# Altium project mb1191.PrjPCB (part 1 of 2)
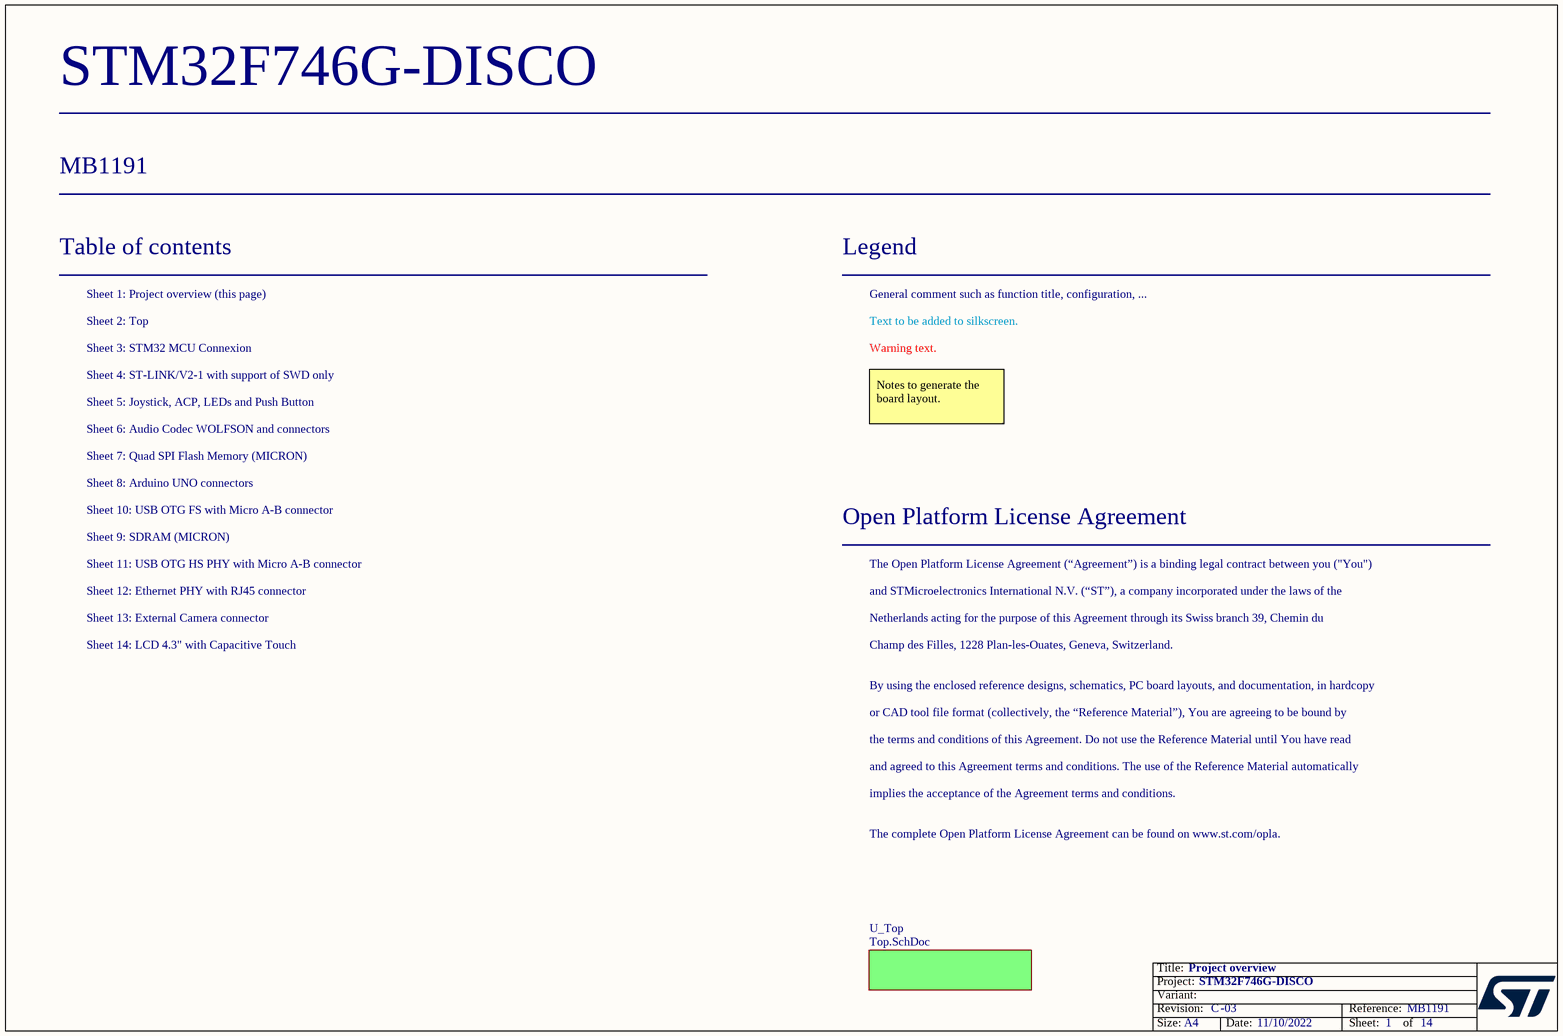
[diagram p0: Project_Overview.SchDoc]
Board_Reference: MB1191; Board_PCB_Revision: C; Board_Name: STM32F746G-DISCO; Board_Document_Date: 11/10/2022; Board_Assembly_Revision: 03
14 sheets, 358 parts. Net scope: flat (ports and power ports of the same name join across sheets).
Board file: MB1191.PcbDoc
Sheets:
  Project_Overview.SchDoc
    U_Top = Top.SchDoc
      U_ST_LINK_V2-1 = ST_LINK_V2-1.SCHDOC
      U_AUDIO = AUDIO.SchDoc
      U_USB_OTG_FS = USB_OTG_FS.SchDoc
      U_Peripherals = Peripherals.SchDoc
      U_QSPI = QSPI.SchDoc
      U_LCD-43 = LCD-43.SchDoc
      U_Arduino_ Connectors = Arduino_ Connectors.SchDoc
      U_SDRAM = SDRAM.SchDoc
      U_USB_OTG_HS = USB_OTG_HS.SchDoc
      U_STM32F7 = STM32F7.SchDoc
      U_Ethernet = Ethernet.SchDoc
      Camera-Connectors = Camera-Connectors.SchDoc

## Sheet Project_Overview.SchDoc: Project overview
size A4; Date: Not used; ApprovedBy: Not used; CheckedBy: Not used; Author: Not used; CompanyName: STMicroelectronics; DrawnBy: Not used; Engineer: Not used; Organization: Not used; Address1: Not used; Address2: Not used; Address3: Not used; Address4: Not used; DocumentNumber: MB1191; Revision: Not used; SheetNumber: 1; SheetTotal: 14

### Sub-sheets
U_Top = Top.SchDoc: no entries

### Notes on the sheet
- Table of contents
- Sheet 1: Project overview (this page)
- Legend
- General comment such as function title, configuration, ...
- Sheet 2: Top
- Sheet 4: ST-LINK/V2-1 with support of SWD only
- Sheet 3: STM32 MCU Connexion
- Text to be added to silkscreen.
- Warning text.
- Sheet 5: Joystick, ACP, LEDs and Push Button
- Sheet 6: Audio Codec WOLFSON and connectors
- Notes to generate the board layout.
- Sheet 8: Arduino UNO connectors
- Sheet 10: USB OTG FS with Micro A-B connector
- Sheet 7: Quad SPI Flash Memory (MICRON)
- Sheet 9: SDRAM (MICRON)
- Sheet 11: USB OTG HS PHY with Micro A-B connector
- Open Platform License Agreement
- The Open Platform License Agreement (“Agreement”) is a binding legal contract between you ("You")
- Sheet 12: Ethernet PHY with RJ45 connector
- Sheet 13: External Camera connector
- Sheet 14: LCD 4.3" with Capacitive Touch
- and STMicroelectronics International N.V. (“ST”), a company incorporated under the laws of the
- Netherlands acting for the purpose of this Agreement through its Swiss branch 39, Chemin du
- Champ des Filles, 1228 Plan-les-Ouates, Geneva, Switzerland.
- By using the enclosed reference designs, schematics, PC board layouts, and documentation, in hardcopy
- or CAD tool file format (collectively, the “Reference Material”), You are agreeing to be bound by
- the terms and conditions of this Agreement. Do not use the Reference Material until You have read
- and agreed to this Agreement terms and conditions. The use of the Reference Material automatically
- implies the acceptance of the Agreement terms and conditions.
- The complete Open Platform License Agreement can be found on www.st.com/opla.

## Sheet Top.SchDoc: STM32F7 Discovery Interconnexion
size A4; Date: 25-FEB-2015; Author: A.B; CompanyName: STMicroelectronics; Address1: 12, Rue Jules HOROWITZ; Address2: 38019 Grenoble; Address3: FRANCE; DocumentNumber: MB1191; Revision: B-02; SheetNumber: 2; SheetTotal: 14; Project: STM32F746G-DISCO
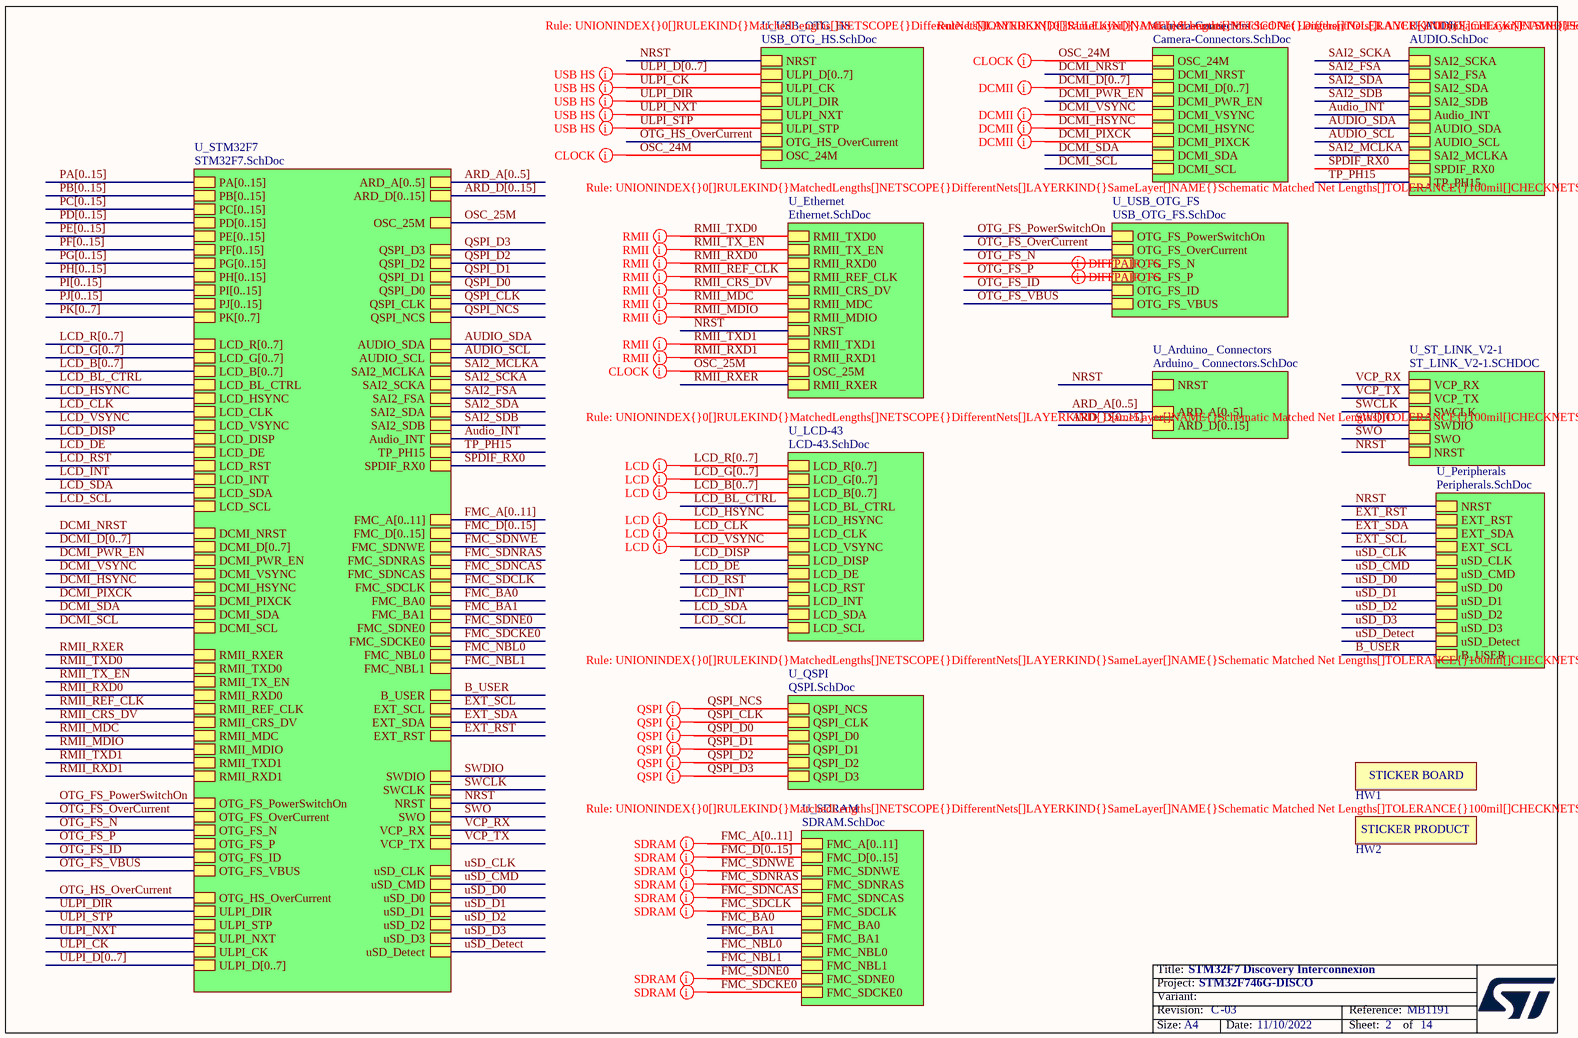
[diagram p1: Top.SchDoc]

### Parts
HW1  STICKER_BOARD  (value not drawn)  (no BOM)
HW2  STICKER_PRODUCT  (value not drawn)  (no BOM)

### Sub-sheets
Camera-Connectors = Camera-Connectors.SchDoc: OSC_24M, DCMI_NRST, DCMI_D[0..7], DCMI_PWR_EN, DCMI_VSYNC, DCMI_HSYNC, DCMI_PIXCK, DCMI_SDA, DCMI_SCL
U_Arduino_ Connectors = Arduino_ Connectors.SchDoc: NRST, ARD_A[0..5], ARD_D[0..15]
U_AUDIO = AUDIO.SchDoc: AUDIO_SDA, AUDIO_SCL, SAI2_MCLKA, SPDIF_RX0, TP_PH15, SAI2_SCKA, SAI2_FSA, SAI2_SDA, SAI2_SDB, Audio_INT
U_Ethernet = Ethernet.SchDoc: RMII_TXD0, RMII_TX_EN, RMII_RXD0, RMII_REF_CLK, RMII_CRS_DV, RMII_MDC, RMII_MDIO, NRST, RMII_TXD1, RMII_RXD1, OSC_25M, RMII_RXER
U_LCD-43 = LCD-43.SchDoc: LCD_R[0..7], LCD_BL_CTRL, LCD_B[0..7], LCD_G[0..7], LCD_HSYNC, LCD_CLK, LCD_VSYNC, LCD_DISP, LCD_DE, LCD_RST, LCD_INT, LCD_SDA, LCD_SCL
U_Peripherals = Peripherals.SchDoc: NRST, EXT_RST, EXT_SCL, EXT_SDA, uSD_CLK, uSD_CMD, uSD_D0, uSD_D1, uSD_D2, uSD_D3, uSD_Detect, B_USER
U_QSPI = QSPI.SchDoc: QSPI_D0, QSPI_D3, QSPI_D1, QSPI_CLK, QSPI_NCS, QSPI_D2
U_SDRAM = SDRAM.SchDoc: FMC_A[0..11], FMC_D[0..15], FMC_SDNWE, FMC_SDNRAS, FMC_SDNCAS, FMC_SDCLK, FMC_BA0, FMC_BA1, FMC_NBL0, FMC_NBL1, FMC_SDNE0, FMC_SDCKE0
U_ST_LINK_V2-1 = ST_LINK_V2-1.SCHDOC: SWDIO, SWCLK, NRST, VCP_RX, VCP_TX, SWO
U_STM32F7 = STM32F7.SchDoc: PA[0..15], PB[0..15], PC[0..15], PD[0..15], PE[0..15], PF[0..15], PG[0..15], PH[0..15], PI[0..15], PJ[0..15], PK[0..7], OSC_25M, LCD_R[0..7], LCD_BL_CTRL, LCD_B[0..7], LCD_G[0..7], LCD_HSYNC, LCD_CLK, LCD_VSYNC, LCD_DISP, LCD_DE, LCD_RST, LCD_INT, LCD_SDA, LCD_SCL, DCMI_NRST, DCMI_D[0..7], DCMI_PWR_EN, DCMI_VSYNC, DCMI_HSYNC, DCMI_PIXCK, DCMI_SDA, DCMI_SCL, RMII_TXD0, RMII_TX_EN, RMII_RXD0, RMII_REF_CLK, RMII_CRS_DV, RMII_MDC, RMII_MDIO, RMII_TXD1, RMII_RXD1, ULPI_D[0..7], ULPI_CK, ULPI_DIR, ULPI_NXT, ULPI_STP, OTG_FS_N, OTG_FS_P, OTG_FS_ID, OTG_FS_VBUS, OTG_FS_PowerSwitchOn, OTG_FS_OverCurrent, QSPI_D0, QSPI_D3, QSPI_D1, QSPI_CLK, QSPI_NCS, AUDIO_SDA, AUDIO_SCL, SAI2_MCLKA, EXT_SCL, EXT_SDA, EXT_RST, uSD_CLK, uSD_CMD, uSD_D0, uSD_D1, uSD_D2, uSD_D3, uSD_Detect, SWDIO, SWCLK, NRST, SWO, VCP_RX, VCP_TX, FMC_A[0..11], FMC_D[0..15], FMC_SDNWE, FMC_SDNRAS, FMC_SDNCAS, FMC_SDCLK, FMC_BA0, FMC_BA1, FMC_SDNE0, FMC_SDCKE0, FMC_NBL0, FMC_NBL1, SPDIF_RX0, QSPI_D2, B_USER, ARD_A[0..5], ARD_D[0..15], RMII_RXER, OTG_HS_OverCurrent, SAI2_SCKA, SAI2_FSA, SAI2_SDA, SAI2_SDB, Audio_INT, TP_PH15
U_USB_OTG_FS = USB_OTG_FS.SchDoc: OTG_FS_PowerSwitchOn, OTG_FS_OverCurrent, OTG_FS_N, OTG_FS_P, OTG_FS_ID, OTG_FS_VBUS
U_USB_OTG_HS = USB_OTG_HS.SchDoc: ULPI_D[0..7], ULPI_CK, ULPI_DIR, ULPI_NXT, ULPI_STP, OSC_24M, NRST, OTG_HS_OverCurrent

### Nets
Audio_INT: sheet U_AUDIO/Audio_INT, sheet U_STM32F7/Audio_INT
AUDIO_SCL: sheet U_AUDIO/AUDIO_SCL, sheet U_STM32F7/AUDIO_SCL
AUDIO_SDA: sheet U_AUDIO/AUDIO_SDA, sheet U_STM32F7/AUDIO_SDA
B_USER: sheet U_Peripherals/B_USER, sheet U_STM32F7/B_USER
DCMI_HSYNC: sheet U_STM32F7/DCMI_HSYNC, sheet Camera-Connectors/DCMI_HSYNC
DCMI_NRST: sheet U_STM32F7/DCMI_NRST, sheet Camera-Connectors/DCMI_NRST
DCMI_PIXCK: sheet U_STM32F7/DCMI_PIXCK, sheet Camera-Connectors/DCMI_PIXCK
DCMI_PWR_EN: sheet U_STM32F7/DCMI_PWR_EN, sheet Camera-Connectors/DCMI_PWR_EN
DCMI_SCL: sheet U_STM32F7/DCMI_SCL, sheet Camera-Connectors/DCMI_SCL
DCMI_SDA: sheet U_STM32F7/DCMI_SDA, sheet Camera-Connectors/DCMI_SDA
DCMI_VSYNC: sheet U_STM32F7/DCMI_VSYNC, sheet Camera-Connectors/DCMI_VSYNC
EXT_RST: sheet U_Peripherals/EXT_RST, sheet U_STM32F7/EXT_RST
EXT_SCL: sheet U_Peripherals/EXT_SCL, sheet U_STM32F7/EXT_SCL
EXT_SDA: sheet U_Peripherals/EXT_SDA, sheet U_STM32F7/EXT_SDA
FMC_BA0: sheet U_SDRAM/FMC_BA0, sheet U_STM32F7/FMC_BA0
FMC_BA1: sheet U_SDRAM/FMC_BA1, sheet U_STM32F7/FMC_BA1
FMC_NBL0: sheet U_SDRAM/FMC_NBL0, sheet U_STM32F7/FMC_NBL0
FMC_NBL1: sheet U_SDRAM/FMC_NBL1, sheet U_STM32F7/FMC_NBL1
FMC_SDCKE0: sheet U_SDRAM/FMC_SDCKE0, sheet U_STM32F7/FMC_SDCKE0
FMC_SDCLK: sheet U_SDRAM/FMC_SDCLK, sheet U_STM32F7/FMC_SDCLK
FMC_SDNCAS: sheet U_SDRAM/FMC_SDNCAS, sheet U_STM32F7/FMC_SDNCAS
FMC_SDNE0: sheet U_SDRAM/FMC_SDNE0, sheet U_STM32F7/FMC_SDNE0
FMC_SDNRAS: sheet U_SDRAM/FMC_SDNRAS, sheet U_STM32F7/FMC_SDNRAS
FMC_SDNWE: sheet U_SDRAM/FMC_SDNWE, sheet U_STM32F7/FMC_SDNWE
LCD_BL_CTRL: sheet U_LCD-43/LCD_BL_CTRL, sheet U_STM32F7/LCD_BL_CTRL
LCD_CLK: sheet U_LCD-43/LCD_CLK, sheet U_STM32F7/LCD_CLK
LCD_DE: sheet U_LCD-43/LCD_DE, sheet U_STM32F7/LCD_DE
LCD_DISP: sheet U_LCD-43/LCD_DISP, sheet U_STM32F7/LCD_DISP
LCD_HSYNC: sheet U_LCD-43/LCD_HSYNC, sheet U_STM32F7/LCD_HSYNC
LCD_INT: sheet U_LCD-43/LCD_INT, sheet U_STM32F7/LCD_INT
LCD_RST: sheet U_LCD-43/LCD_RST, sheet U_STM32F7/LCD_RST
LCD_SCL: sheet U_LCD-43/LCD_SCL, sheet U_STM32F7/LCD_SCL
LCD_SDA: sheet U_LCD-43/LCD_SDA, sheet U_STM32F7/LCD_SDA
LCD_VSYNC: sheet U_LCD-43/LCD_VSYNC, sheet U_STM32F7/LCD_VSYNC
NRST: sheet U_ST_LINK_V2-1/NRST, sheet U_Peripherals/NRST, sheet U_Arduino_ Connectors/NRST, sheet U_USB_OTG_HS/NRST, sheet U_STM32F7/NRST, sheet U_Ethernet/NRST
OSC_24M: sheet U_USB_OTG_HS/OSC_24M, sheet Camera-Connectors/OSC_24M
OSC_25M: sheet U_STM32F7/OSC_25M, sheet U_Ethernet/OSC_25M
OTG_FS_ID: sheet U_USB_OTG_FS/OTG_FS_ID, sheet U_STM32F7/OTG_FS_ID
OTG_FS_N: sheet U_USB_OTG_FS/OTG_FS_N, sheet U_STM32F7/OTG_FS_N
OTG_FS_OverCurrent: sheet U_USB_OTG_FS/OTG_FS_OverCurrent, sheet U_STM32F7/OTG_FS_OverCurrent
OTG_FS_P: sheet U_USB_OTG_FS/OTG_FS_P, sheet U_STM32F7/OTG_FS_P
OTG_FS_PowerSwitchOn: sheet U_USB_OTG_FS/OTG_FS_PowerSwitchOn, sheet U_STM32F7/OTG_FS_PowerSwitchOn
OTG_FS_VBUS: sheet U_USB_OTG_FS/OTG_FS_VBUS, sheet U_STM32F7/OTG_FS_VBUS
OTG_HS_OverCurrent: sheet U_USB_OTG_HS/OTG_HS_OverCurrent, sheet U_STM32F7/OTG_HS_OverCurrent
QSPI_CLK: sheet U_QSPI/QSPI_CLK, sheet U_STM32F7/QSPI_CLK
QSPI_D0: sheet U_QSPI/QSPI_D0, sheet U_STM32F7/QSPI_D0
QSPI_D1: sheet U_QSPI/QSPI_D1, sheet U_STM32F7/QSPI_D1
QSPI_D2: sheet U_QSPI/QSPI_D2, sheet U_STM32F7/QSPI_D2
QSPI_D3: sheet U_QSPI/QSPI_D3, sheet U_STM32F7/QSPI_D3
QSPI_NCS: sheet U_QSPI/QSPI_NCS, sheet U_STM32F7/QSPI_NCS
RMII_CRS_DV: sheet U_STM32F7/RMII_CRS_DV, sheet U_Ethernet/RMII_CRS_DV
RMII_MDC: sheet U_STM32F7/RMII_MDC, sheet U_Ethernet/RMII_MDC
RMII_MDIO: sheet U_STM32F7/RMII_MDIO, sheet U_Ethernet/RMII_MDIO
RMII_REF_CLK: sheet U_STM32F7/RMII_REF_CLK, sheet U_Ethernet/RMII_REF_CLK
RMII_RXD0: sheet U_STM32F7/RMII_RXD0, sheet U_Ethernet/RMII_RXD0
RMII_RXD1: sheet U_STM32F7/RMII_RXD1, sheet U_Ethernet/RMII_RXD1
RMII_RXER: sheet U_STM32F7/RMII_RXER, sheet U_Ethernet/RMII_RXER
RMII_TX_EN: sheet U_STM32F7/RMII_TX_EN, sheet U_Ethernet/RMII_TX_EN
RMII_TXD0: sheet U_STM32F7/RMII_TXD0, sheet U_Ethernet/RMII_TXD0
RMII_TXD1: sheet U_STM32F7/RMII_TXD1, sheet U_Ethernet/RMII_TXD1
SAI2_FSA: sheet U_AUDIO/SAI2_FSA, sheet U_STM32F7/SAI2_FSA
SAI2_MCLKA: sheet U_AUDIO/SAI2_MCLKA, sheet U_STM32F7/SAI2_MCLKA
SAI2_SCKA: sheet U_AUDIO/SAI2_SCKA, sheet U_STM32F7/SAI2_SCKA
SAI2_SDA: sheet U_AUDIO/SAI2_SDA, sheet U_STM32F7/SAI2_SDA
SAI2_SDB: sheet U_AUDIO/SAI2_SDB, sheet U_STM32F7/SAI2_SDB
SPDIF_RX0: sheet U_AUDIO/SPDIF_RX0, sheet U_STM32F7/SPDIF_RX0
SWCLK: sheet U_ST_LINK_V2-1/SWCLK, sheet U_STM32F7/SWCLK
SWDIO: sheet U_ST_LINK_V2-1/SWDIO, sheet U_STM32F7/SWDIO
SWO: sheet U_ST_LINK_V2-1/SWO, sheet U_STM32F7/SWO
TP_PH15: sheet U_AUDIO/TP_PH15, sheet U_STM32F7/TP_PH15
ULPI_CK: sheet U_USB_OTG_HS/ULPI_CK, sheet U_STM32F7/ULPI_CK
ULPI_DIR: sheet U_USB_OTG_HS/ULPI_DIR, sheet U_STM32F7/ULPI_DIR
ULPI_NXT: sheet U_USB_OTG_HS/ULPI_NXT, sheet U_STM32F7/ULPI_NXT
ULPI_STP: sheet U_USB_OTG_HS/ULPI_STP, sheet U_STM32F7/ULPI_STP
uSD_CLK: sheet U_Peripherals/uSD_CLK, sheet U_STM32F7/uSD_CLK
uSD_CMD: sheet U_Peripherals/uSD_CMD, sheet U_STM32F7/uSD_CMD
uSD_D0: sheet U_Peripherals/uSD_D0, sheet U_STM32F7/uSD_D0
uSD_D1: sheet U_Peripherals/uSD_D1, sheet U_STM32F7/uSD_D1
uSD_D2: sheet U_Peripherals/uSD_D2, sheet U_STM32F7/uSD_D2
uSD_D3: sheet U_Peripherals/uSD_D3, sheet U_STM32F7/uSD_D3
uSD_Detect: sheet U_Peripherals/uSD_Detect, sheet U_STM32F7/uSD_Detect
VCP_RX: sheet U_ST_LINK_V2-1/VCP_RX, sheet U_STM32F7/VCP_RX
VCP_TX: sheet U_ST_LINK_V2-1/VCP_TX, sheet U_STM32F7/VCP_TX

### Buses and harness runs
bus ARD_A[0..5] = sheet U_Arduino_ Connectors/ARD_A[0..5]
bus ARD_A[0..5] = sheet U_STM32F7/ARD_A[0..5]
bus ARD_D[0..15] = sheet U_Arduino_ Connectors/ARD_D[0..15]
bus ARD_D[0..15] = sheet U_STM32F7/ARD_D[0..15]
bus DCMI_D[0..7] = sheet Camera-Connectors/DCMI_D[0..7]
bus DCMI_D[0..7] = sheet U_STM32F7/DCMI_D[0..7]
bus FMC_A[0..11] = sheet U_SDRAM/FMC_A[0..11]
bus FMC_A[0..11] = sheet U_STM32F7/FMC_A[0..11]
bus FMC_D[0..15] = sheet U_SDRAM/FMC_D[0..15]
bus FMC_D[0..15] = sheet U_STM32F7/FMC_D[0..15]
bus LCD_B[0..7] = sheet U_LCD-43/LCD_B[0..7]
bus LCD_B[0..7] = sheet U_STM32F7/LCD_B[0..7]
bus LCD_G[0..7] = sheet U_LCD-43/LCD_G[0..7]
bus LCD_G[0..7] = sheet U_STM32F7/LCD_G[0..7]
bus LCD_R[0..7] = sheet U_LCD-43/LCD_R[0..7]
bus LCD_R[0..7] = sheet U_STM32F7/LCD_R[0..7]
bus PA[0..15] = sheet U_STM32F7/PA[0..15]
bus PB[0..15] = sheet U_STM32F7/PB[0..15]
bus PC[0..15] = sheet U_STM32F7/PC[0..15]
bus PD[0..15] = sheet U_STM32F7/PD[0..15]
bus PE[0..15] = sheet U_STM32F7/PE[0..15]
bus PF[0..15] = sheet U_STM32F7/PF[0..15]
bus PG[0..15] = sheet U_STM32F7/PG[0..15]
bus PH[0..15] = sheet U_STM32F7/PH[0..15]
bus PI[0..15] = sheet U_STM32F7/PI[0..15]
bus PJ[0..15] = sheet U_STM32F7/PJ[0..15]
bus PK[0..7] = sheet U_STM32F7/PK[0..7]
bus ULPI_D[0..7] = sheet U_STM32F7/ULPI_D[0..7]
bus ULPI_D[0..7] = sheet U_USB_OTG_HS/ULPI_D[0..7]

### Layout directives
rule Matched Net Lengths [Tolerance = 100mil]: (no net found under the mark), DCMI_HSYNC, DCMI_PIXCK, DCMI_VSYNC, FMC_SDCKE0, FMC_SDCLK, FMC_SDNCAS, FMC_SDNE0, FMC_SDNRAS, FMC_SDNWE, LCD_CLK, LCD_HSYNC, LCD_VSYNC, QSPI_CLK, QSPI_D0, QSPI_D1, QSPI_D2, QSPI_D3, QSPI_NCS, RMII_CRS_DV, RMII_MDC, RMII_MDIO, RMII_REF_CLK, RMII_RXD0, RMII_RXD1, RMII_TX_EN, RMII_TXD0, RMII_TXD1, ULPI_CK, ULPI_DIR, ULPI_NXT, ULPI_STP
rule Undefined: OSC_24M, OSC_25M
differential pair: OTG_FS_N, OTG_FS_P

## Sheet ST_LINK_V2-1.SCHDOC: ST-LINK/V2-1 with support of SWD only
size A4; Date: 25-FEB-2015; Author: A.B; CompanyName: STMicroelectronics; Address1: 12, Rue Jules HOROWITZ; Address2: 38019 Grenoble; Address3: FRANCE; DocumentNumber: MB1191; Revision: B-02; SheetNumber: 4; SheetTotal: 14; Project: STM32F746G-DISCO
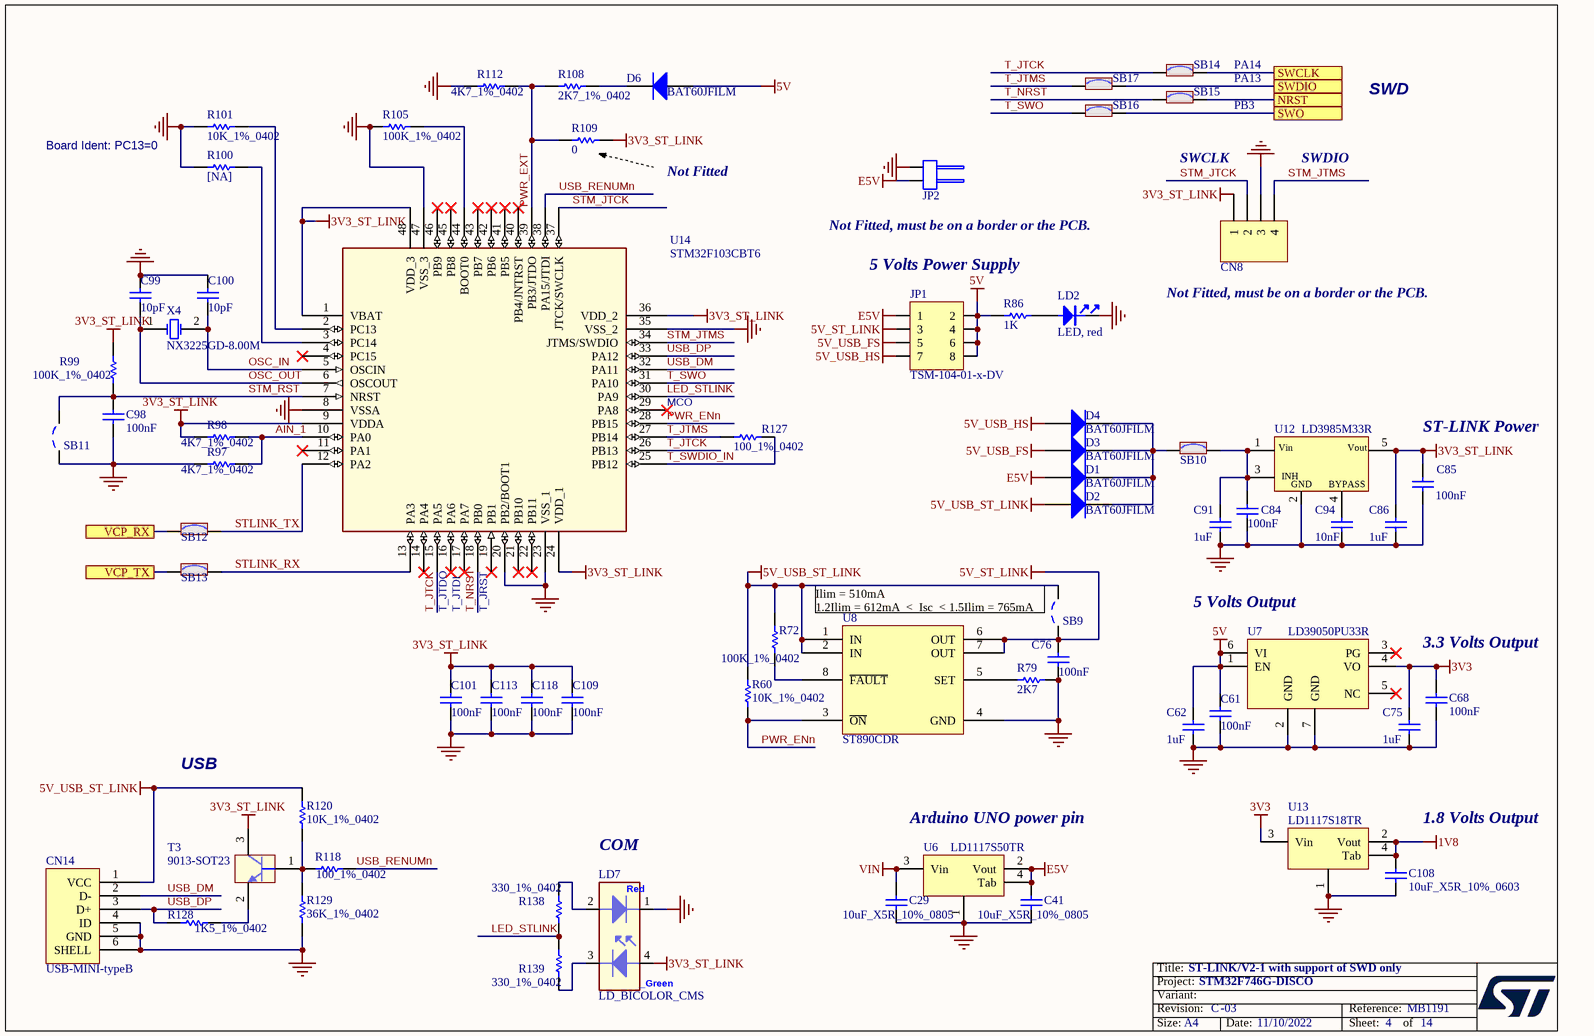
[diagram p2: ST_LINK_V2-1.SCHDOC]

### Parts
C29  10uF_X5R_10%_0805  [0805C]
C41  10uF_X5R_10%_0805  [0805C]
C61  100nF  [0402C]
C62  1uF  [0603C]
C68  100nF  [0402C]
C75  1uF  [0603C]
C76  100nF  [0402C]
C84  100nF  [0402C]
C85  100nF  [0402C]
C86  1uF  [0603C]
C91  1uF  [0603C]
C94  10nF  [0603C]
C98  100nF  [0402C]
C99  10pF  [0402C]
C100  10pF  [0402C]
C101  100nF  [0402C]
C108  10uF_X5R_10%_0603  [0603C]
C109  100nF  [0402C]
C113  100nF  [0402C]
C118  100nF  [0402C]
CN8  Header 4  [Header 4]  (value not drawn)
CN14  USB-MINI-typeB  [USB-MINI-B-SMD]
D1  BAT60JFILM  [SOD323/A]
D2  BAT60JFILM  [SOD323/A]
D3  BAT60JFILM  [SOD323/A]
D4  BAT60JFILM  [SOD323/A]
D6  BAT60JFILM  [SOD323/A]
JP1  TSM-104-01-x-DV  [TSM-104-01-x-DV]
JP2  TSM-102-01-F-SH-A  [TSM-102-01-F-SH-A]  (value not drawn)
LD2  LED, red  [0603D]
LD7  LD_BICOLOR_CMS  [HSMF-A201]
R60  10K_1%_0402  [0402R]
R72  100K_1%_0402  [0402R]
R79  2K7  [0402R]
R86  1K  [0402R]
R97  4K7_1%_0402  [0402R]
R98  4K7_1%_0402  [0402R]
R99  100K_1%_0402  [0402R]
R100  [NA]  [0402R]
R101  10K_1%_0402  [0402R]
R105  100K_1%_0402  [0402R]
R108  2K7_1%_0402  [0402R]
R109  0  [0402R]
R112  4K7_1%_0402  [0402R]
R118  100_1%_0402  [0402R]
R120  10K_1%_0402  [0402R]
R127  100_1%_0402  [0402R]
R128  1K5_1%_0402  [0402R]
R129  36K_1%_0402  [0402R]
R138  330_1%_0402  [0402R]
R139  330_1%_0402  [0402R]
SB9  Solder Bridge OFF  [JP2_SMD]  (value not drawn)
SB10  Solder Bridge ON  [JP2_SMD]  (value not drawn)
SB11  Solder Bridge OFF  [JP2_SMD]  (value not drawn)
SB12  Solder Bridge ON  [JP2_SMD]  (value not drawn)
SB13  Solder Bridge ON  [JP2_SMD]  (value not drawn)
SB14  Solder Bridge ON  [JP2_SMD]  (value not drawn)
SB15  Solder Bridge ON  [JP2_SMD]  (value not drawn)
SB16  Solder Bridge ON  [JP2_SMD]  (value not drawn)
SB17  Solder Bridge ON  [JP2_SMD]  (value not drawn)
T3  9013-SOT23  [SOT23]
U6  LD1117S50TR  [SOT-223]
U7  LD39050PU33R  [DFN6_3x3]
U8  ST890CDR  [SO-8]
U12  LD3985M33R  [SOT23-5L]
U13  LD1117S18TR  [SOT-223]
U14  STM32F103CBT6  [QFP48 7x7]
X4  NX3225GD-8.00M  [XTAL_2SM_3R2X2R5]

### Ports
NRST, SWCLK, SWDIO, SWO, VCP_RX, VCP_TX

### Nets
1V8: C108.2 U13.2(Vout) U13.4(Tab)
3V3: C68.2 C75.2 U7.4(VO) U13.3(Vin)
3V3_ST_LINK: C85.2 C86.1 C101.2 C109.2 C113.2 C118.1 CN8.1 LD7.4 R98.1 R99.2 R109.2 T3.3(C) U12.5(Vout) U14.1(VBAT) U14.9(VDDA) U14.24(VDD_1) U14.36(VDD_2) U14.48(VDD_3)
5V: C61.2 C62.2 D6.1(A) JP1.2 JP1.4 JP1.6 JP1.8 R86.1 U7.1(EN) U7.6(VI)
5V_ST_LINK: C76.2 JP1.3 SB9.1 U8.6(OUT) U8.7(OUT)
5V_USB_FS: D3.1(A) JP1.5
5V_USB_HS: D4.1(A) JP1.7
5V_USB_ST_LINK: CN14.1(VCC) D2.1(A) R60.2 R72.2 R120.2 SB9.2 U8.1(IN) U8.2(IN)
E5V: C41.2 D1.1(A) JP1.1 JP2.2(NO) U6.2(Vout) U6.4(Tab)
GND: C29.1 C41.1 C61.1 C62.1 C68.1 C75.1 C76.1 C84.1 C85.1 C86.2 C91.1 C94.1 C98.1 C99.1 C100.1 C101.1 C108.1 C109.1 C113.1 C118.2 CN8.3 CN14.4(ID) CN14.5(GND) CN14.6(SHELL) JP2.1(COMMON) LD2.2 LD7.1 R79.2 R97.1 R100.1 R101.1 R105.1 R112.1 R129.1 SB11.1 U6.1 U7.2(GND) U7.7(GND) U8.4(GND) U12.2(GND) U13.1 U14.8(VSSA) U14.20(PB2/BOOT1) U14.23(VSS_1) U14.35(VSS_2) U14.47(VSS_3)
VIN: C29.2 U6.3(Vin)
AIN_1: R97.2 R98.2 U14.10(PA0)
DCMI_NRST: SB15.2 ; port NRST
LED_STLINK: R138.1 R139.2 U14.30(PA9)
OSC_IN: C100.2 U14.5(OSCIN) X4.2(OSC2)
OSC_OUT: C99.2 U14.6(OSCOUT) X4.1(OSC1)
PA13: SB17.2 ; port SWDIO
PA14: SB14.2 ; port SWCLK
PB3: SB16.2 ; port SWO
PB7: SB12.1 ; port VCP_RX
PWR_ENn: R60.1 U8.3(~{ON}) U14.28(PB15)
PWR_EXT: R108.1 R109.1 R112.2 U14.39(PB3/JTDO)
STLINK_RX: SB13.2 U14.13(PA3)
STLINK_TX: SB12.2 U14.12(PA2)
STM_JTCK: CN8.2 U14.37(JTCK/SWCLK)
STM_JTMS: CN8.4 U14.34(JTMS/SWDIO)
STM_RST: C98.2 R99.1 SB11.2 U14.7(NRST)
T_JTCK: SB14.1 U14.15(PA5) U14.26(PB13)
T_JTMS: R127.1 SB17.1 U14.27(PB14)
T_NRST: SB15.1 U14.18(PB0)
T_SWDIO_IN: R127.2 U14.25(PB12)
T_SWO: SB16.1 U14.31(PA10)
USB_DM: CN14.2(D-) U14.32(PA11)
USB_DP: CN14.3(D+) R128.1 U14.33(PA12)
USB_RENUMn: R118.2 U14.38(PA15/JTDI)
VCP_TX: SB13.1 ; port VCP_TX
NetC84_2: C84.2 C91.2 SB10.2 U12.1(Vin) U12.3(CE)
NetC94_2: C94.2 U12.4(BYPASS)
NetD1_2: D1.2(K) D2.2(K) D3.2(K) D4.2(K) SB10.1
NetD6_2: D6.2(K) R108.2
NetLD2_1: LD2.1 R86.2
NetLD7_2: LD7.2 R138.2
NetLD7_3: LD7.3 R139.1
NetR72_1: R72.1 U8.8(~{FAULT})
NetR79_1: R79.1 U8.5(SET)
NetR100_2: R100.2 U14.3(PC14)
NetR101_2: R101.2 U14.2(PC13)
NetR105_2: R105.2 U14.44(BOOT0)
NetR118_1: R118.1 R120.1 R129.2 T3.1(B)
NetR128_2: R128.2 T3.2(E)

Not connected (* = marked no-connect by the designer): U7 3(PG)* 5(NC)*; U14 4(PC15)* 11(PA1)* 14(PA4)* 16(PA6)* 17(PA7)* 19(PB1)* 21(PB10)* 22(PB11)* 29(PA8)* 40(PB4/JNTRST)* 41(PB5)* 42(PB6)* 43(PB7)* 45(PB8)* 46(PB9)*

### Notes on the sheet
- PA14
- PA13
- PB3
- SWD
- Board Ident: PC13=0
- Not Fitted
- SWCLK
- SWDIO
- (near JP2) Not Fitted, must be on a border or the PCB.
- 5 Volts Power Supply
- Not Fitted, must be on a border or the PCB.
- MCO
- ST-LINK Power
- (near U14) T_JTDO
- (near U14) T_JTDI
- (near U14) T_JRST
- (near SB9) Ilim = 510mA
  1.2Ilim = 612mA  <  Isc  < 1.5Ilim = 765mA
- 5 Volts Output
- 3.3 Volts Output
- USB
- COM
- (near U6) Arduino UNO power pin
- 1.8 Volts Output

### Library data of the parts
C29 C41 = Cap_10uF_X5R_10%_0805: Capacitor,10uF,25V,X5R,10%,0805,YAGEO; Manuf_Part_1: CC0805KRX5R8BB106
C61 C68 C76 C84 C85 C98 C101 C109 C113 C118 = Cap_100nF_X7R_10%_0402: Capacitor,100nF,16V,X7R,10%,0402,YAGEO; Manuf_Part_1: CC0402KRX7R7BB104
C62 C75 C86 C91 = Cap_1uF_X5R_10%_0603: Capacitor,1uF,16V,X5R,10%,0603,YAGEO; Manuf_Part_1: CC0603KRX5R7BB105
C94 = Cap_10nF_X7R_10%_0603: Capacitor,10nF,50V,X7R,10%,0603,YAGEO; Manuf_Part_1: CC0603KRX7R9BB103
C99 C100 = Cap_10pF_NPO_5%_0402: Capacitor,10pF,50V,NPO,5%,0402,YAGEO; Order: CC0402JRNPO9BN100
C108 = Cap_10uF_X5R_10%_0603: Capacitor,10uF,6.3V,X5R,10%,0603,YAGEO; Manuf_Part_1: CC0603KRX5R5BB106
CN8 = Header 4: Header, 4-Pin; Fitted: NO
CN14 = USB-MINI-typeB connector: Manuf_Part_1: 5075BMR-05-SM; Manuf_Part_2: 218205M1110T; Manuf_2: lyconn; Manuf_Part_3: MUSB5QS-BM1H6-NLB-E; Manuf_3: TOWNES
D1-D4 D6 = BAT60JFILM: Manuf_1: STM; Provided: ST; ECCN_US/EU: EAR99/NEC; Ref St: 9151097
JP1 = Header_4X2_SMD: Header, 4-Pins, Double row Vertical, SMD, 2.54; Manuf_1: SAMTEC
JP2 = JP2_CMS: Header, 2-Pins, Single row Horizontal SMD, 2.54; Manuf_1: SAMTEC; ECCN_US/EU: EAR99/NEC
LD2 = LED_red: LED, red, 0603; Manuf_1: everlight; Manuf_Part_1: 19-217/R6C-AL1M2VY/3T; ECCN_US/EU: EAR99/NEC
LD7 = LD_BICOLOR_CMS: Bicolor Led; Manuf_Part_1: HSMF-A201-A00J1; Manuf_1: Avago Technologies; Manuf_2: everluck; Manuf_Part_2: LE-RGW35280; Ref St: xxxxxx; ECCN_US/EU: EAR99/NEC
R60 R101 R120 = Res_10K_1%_0402: Resistor,10K,0402,1%,YAGEO; Manuf_Part_1: RC0402FR-0710KL
R72 R99 R105 = Res_100K_1%_0402: Resistor,100K,0402,1%,YAGEO; Manuf_Part_1: RT0402FRE07100KL
R79 R108 = Res_2K7_1%_0402: Resistor,2K7,0402,1%,YAGEO; Manuf_Part_1: RC0402FR-072K7L
R86 = Res_1K_1%_0402: Resistor,1K,0402,1%,YAGEO; Manuf_Part_1: RC0402FR-071KL
R97 R98 R112 = Res_4K7_1%_0402: Resistor,4K7,0402,1%,YAGEO; Manuf_Part_1: RT0402FRE074K7L
R100 = Res_NA_0402: Resistor,[NA],0402; Fitted: NO
R109 = Res_0_5%_0402: Resistor,0,0402,5%,YAGEO; Manuf_Part_1: RC0402JR-070RL; Order: 2363467; Fitted: NO
R118 R127 = Res_100_1%_0402: Resistor,100,0402,1%,YAGEO; Manuf_Part_1: RC0402FR-07100RL; Value: 100; Order: 9239111
R128 = Res_1K5_1%_0402: Resistor,1K5,0402,1%,YAGEO; Manuf_Part_1: RC0402FR-071K5L
R129 = Res_36K_1%_0402: Resistor,36K,0402,1%,YAGEO; Manuf_Part_1: RC0402FR-0736KL
R138 R139 = Res_330_1%_0402: Resistor,330,0402,1%,YAGEO; Manuf_Part_1: RC0402FR-07330RL; Value: 330
SB9 SB11 = SB_OFF: Solder: NO
SB10 SB12-SB17 = SB_ON: Solder: YES
T3 = 9013-SOT23: NPN Bipolar Transistor; Manuf_1: NXP; Manuf_Part_1: BSR14; Order: 1081310; ECCN_US/EU: EAR99/NEC
U6 = LD1117S50TR: IC REG LDO 5V 0.8A SOT223; Manuf_1: STM; Ordered by: ST; ECCN_US/EU: EAR99/NEC; Ref St: 9176133
U7 = LD39050P: Ultra low drop-low , 500 mA low quiescent current; Manuf_1: STM; Provided: ST; ECCN_US/EU: EAR99/NEC; Ref St: xxxxxxxx
U8 = ST890CDR: 1.2 A current limited high-side power switch with thermal shutdown; Manuf_1: STM; ECCN_US/EU: EAR99/NEC; Provided: ST
U12 = LD3985M33R: Ultra low drop-low noise BiCMOS voltage, regulators low ESR capacitors compatible; Manuf_1: STM; Provided: ST; Ref St: 9176161; ECCN_US/EU: EAR99/NEC
U13 = LD1117S18TR: LOW DROP FIXED AND ADJUSTABLE POSITIVE VOLTAGE REGULATORS (1.8 Volts); Manuf_1: STM; Ref St: 9176180; ECCN_US/EU: EAR99/NEC; Provided: ST
U14 = STM32F103CBT6: Medium-density performance line ARM-based 32-bit MCU with 128KB Flash; Manuf_1: STM; Ref St: xxxxxxxx; Provided: ST; ECCN_US/EU: 3A991A2/NEC
X4 = XTAL_8M_NX3225GD: Crystal 8Mhz, 8pF, -+50PPM, SMD; Manuf_1: NDK; Manuf_Part_1: NX3225GD 8MHz EXS00A-CG04874; Manuf_Part_2: NX3225GD-8.000M-STD-CRA-3; ECCN_US/EU: EAR99/NEC; NDK Ref: X3127326; Ref St: 9157029; Provided: ST

## Sheet AUDIO.SchDoc: Audio Codec WOLFSON and connectors
size A4; Date: 25-FEB-2015; Author: A.B; CompanyName: STMicroelectronics; Address1: 12, Rue Jules HOROWITZ; Address2: 38019 Grenoble; Address3: FRANCE; DocumentNumber: MB1191; Revision: B-02; SheetNumber: 6; SheetTotal: 14; Project: STM32F746G-DISCO
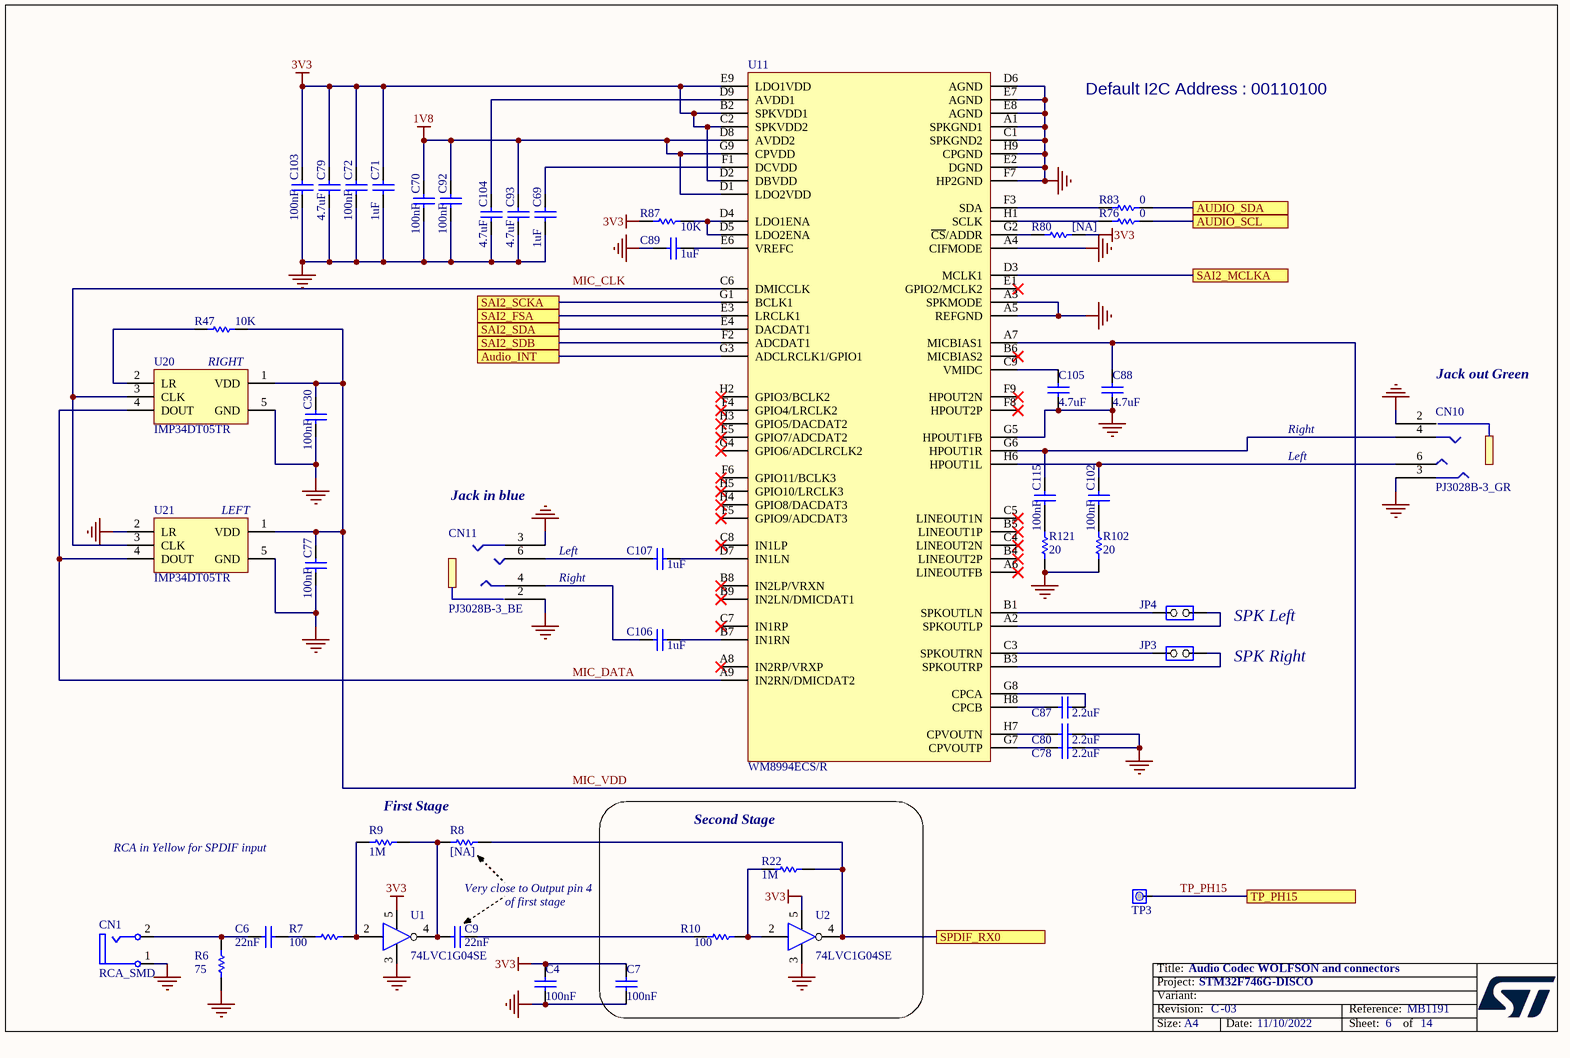
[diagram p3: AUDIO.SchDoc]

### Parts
C4  100nF  [0402C]
C6  22nF  [0402C]
C7  100nF  [0402C]
C9  22nF  [0402C]
C30  100nF  [0402C]
C69  1uF  [0603C]
C70  100nF  [0402C]
C71  1uF  [0603C]
C72  100nF  [0402C]
C77  100nF  [0402C]
C78  2.2uF  [0603C]
C79  4.7uF  [0603C]
C80  2.2uF  [0603C]
C87  2.2uF  [0603C]
C88  4.7uF  [0603C]
C89  1uF  [0603C]
C92  100nF  [0402C]
C93  4.7uF  [0603C]
C102  100nF  [0402C]
C103  100nF  [0402C]
C104  4.7uF  [0603C]
C105  4.7uF  [0603C]
C106  1uF  [0603C]
C107  1uF  [0603C]
C115  100nF  [0402C]
CN1  RCA_SMD  [RCA_SMD]
CN10  PJ3028B-3_GR  [PJ3028B]
CN11  PJ3028B-3_BE  [PJ3028B]
JP3  Jumper 2 pins  [SIP2/2.54]  (value not drawn)
JP4  Jumper 2 pins  [SIP2/2.54]  (value not drawn)
R6  75  [0402R]
R7  100  [0402R]
R8  [NA]  [0402R]
R9  1M  [0402R]
R10  100  [0402R]
R22  1M  [0402R]
R47  10K  [0402R]
R76  0  [0402R]
R80  [NA]  [0402R]
R83  0  [0402R]
R87  10K  [0402R]
R102  20  [0402R]
R121  20  [0402R]
TP3  Test point 1 pin with hole  [SIP1/2.54]  (value not drawn)
U1  74LVC1G04SE  [SOT353]
U2  74LVC1G04SE  [SOT353]
U11  WM8994ECS/R  [BGA72_0R5_4R5X4]
U20  IMP34DT05TR  [HCLGA_3X4X1_4LD]
U21  IMP34DT05TR  [HCLGA_3X4X1_4LD]

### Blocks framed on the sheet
Second Stage: C7 R10 R22 U2

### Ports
Audio_INT, AUDIO_SCL, AUDIO_SDA, SAI2_FSA, SAI2_MCLKA, SAI2_SCKA, SAI2_SDA, SAI2_SDB, SPDIF_RX0, TP_PH15

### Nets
1V8: C70.1 C92.1 C93.1 U11.D1(LDO2VDD) U11.D8(AVDD2) U11.G9(CPVDD)
3V3: C4.2 C7.2 C71.2 C72.1 C79.1 C103.1 R80.2 R87.2 U1.5(VCC) U2.5(VCC) U11.B2(SPKVDD1) U11.C2(SPKVDD2) U11.D2(DBVDD) U11.E9(LDO1VDD)
GND: C4.1 C7.1 C30.2 C69.1 C70.2 C71.1 C72.2 C77.2 C78.2 C79.2 C80.2 C88.1 C89.2 C92.2 C93.2 C103.2 C104.2 C105.1 CN1.1(Ground) CN10.2 CN10.3 CN11.2 CN11.3 R6.1 R102.2 R121.2 U1.3(GND) U2.3(GND) U11.A1(SPKGND1) U11.A3(SPKMODE) U11.A4(CIFMODE) U11.A5(REFGND) U11.C1(SPKGND2) U11.D6(AGND) U11.E2(DGND) U11.E7(AGND) U11.E8(AGND) U11.F7(HP2GND) U11.G5(HPOUT1FB) U11.H9(CPGND) U20.5(GND) U21.2(LR) U21.5(GND)
Audio_INT: U11.G3(ADCLRCLK1/GPIO1) ; port Audio_INT
AUDIO_SCL: R76.1 ; port AUDIO_SCL
AUDIO_SDA: R83.1 ; port AUDIO_SDA
MIC_CLK: U11.C6(DMICCLK) U20.3(CLK) U21.3(CLK)
MIC_DATA: U11.A9(IN2RN/DMICDAT2) U20.4(DOUT) U21.4(DOUT)
MIC_VDD: C30.1 C77.1 C88.2 R47.2 U11.A7(MICBIAS1) U20.1(VDD) U21.1(VDD)
PD7: R8.2 R22.2 U2.4(Y) ; port SPDIF_RX0
PG10: U11.F2(ADCDAT1) ; port SAI2_SDB
PI4: U11.D3(MCLK1) ; port SAI2_MCLKA
PI5: U11.G1(BCLK1) ; port SAI2_SCKA
PI6: U11.E4(DACDAT1) ; port SAI2_SDA
PI7: U11.E3(LRCLK1) ; port SAI2_FSA
TP_PH15: TP3.1(COMMON) ; port TP_PH15  [project net PH15]
NetC6_1: C6.1 CN1.2(Signal) R6.2
NetC6_2: C6.2 R7.1
NetC9_1: C9.1 R8.1 R9.2 U1.4(Y)
NetC9_2: C9.2 R10.1
NetC69_2: C69.2 U11.F1(DCVDD)
NetC78_1: C78.1 U11.G7(CPVOUTP)
NetC80_1: C80.1 U11.H7(CPVOUTN)
NetC87_1: C87.1 U11.H8(CPCB)
NetC87_2: C87.2 U11.G8(CPCA)
NetC89_1: C89.1 U11.E6(VREFC)
NetC102_1: C102.1 CN10.6 U11.H6(HPOUT1L)
NetC102_2: C102.2 R102.1
NetC104_1: C104.1 U11.D9(AVDD1)
NetC105_2: C105.2 U11.C9(VMIDC)
NetC106_1: C106.1 U11.B7(IN1RN)
NetC106_2: C106.2 CN11.4
NetC107_1: C107.1 U11.D7(IN1LN)
NetC107_2: C107.2 CN11.6
NetC115_1: C115.1 CN10.4 U11.G6(HPOUT1R)
NetC115_2: C115.2 R121.1
NetJP3_1: JP3.1(COMMON) U11.C3(SPKOUTRN)
NetJP3_2: JP3.2(NO) U11.B3(SPKOUTRP)
NetJP4_1: JP4.1(COMMON) U11.B1(SPKOUTLN)
NetJP4_2: JP4.2(NO) U11.A2(SPKOUTLP)
NetR7_2: R7.2 R9.1 U1.2(A)
NetR10_2: R10.2 R22.1 U2.2(A)
NetR47_1: R47.1 U20.2(LR)
NetR76_2: R76.2 U11.H1(SCLK)
NetR80_1: R80.1 U11.G2(~{CS}/ADDR)
NetR83_2: R83.2 U11.F3(SDA)
NetR87_1: R87.1 U11.D4(LDO1ENA) U11.D5(LDO2ENA)

Not connected (* = marked no-connect by the designer): U1 1(NC); U2 1(NC); U11 A6(LINEOUTFB)* A8(IN2RP/VRXP)* B4(LINEOUT2P)* B5(LINEOUT1P)* B6(MICBIAS2)* B8(IN2LP/VRXN)* B9(IN2LN/DMICDAT1)* C4(LINEOUT2N)* C5(LINEOUT1N)* C7(IN1RP)* C8(IN1LP)* E1(GPIO2/MCLK2)* E5(GPIO7/ADCDAT2)* F4(GPIO4/LRCLK2)* F5(GPIO9/ADCDAT3)* F6(GPIO11/BCLK3)* F8(HPOUT2P)* F9(HPOUT2N)* G4(GPIO6/ADCLRCLK2)* H2(GPIO3/BCLK2)* H3(GPIO5/DACDAT2)* H4(GPIO8/DACDAT3)* H5(GPIO10/LRCLK3)*

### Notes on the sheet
- Default I2C Address : 00110100
- (near U20) RIGHT
- (near CN10) Jack out Green
- Right
- (near U21) LEFT
- (near CN11) Jack in blue
- Left
- SPK Left
- SPK Right
- RCA in Yellow for SPDIF input
- First Stage
- Very close to Output pin 4
- of first stage

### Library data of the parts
C4 C7 C30 C70 C72 C77 C92 C102 C103 C115 = Cap_100nF_X7R_10%_0402: as C61 on sheet ST_LINK_V2-1
C6 C9 = Cap_22nF_X7R_10%_0402: Capacitor,22nF,16V,X7R,10%,0402,YAGEO; Manuf_Part_1: CC0402KRX7R7BB223
C69 C71 C89 C106 C107 = Cap_1uF_X5R_10%_0603: as C62 on sheet ST_LINK_V2-1
C78 C80 C87 = Cap_2.2uF_X5R_10%_0603: Capacitor,2.2uF,10V, X5R,10%,0603,YAGEO; Manuf_Part_1: CC0603KRX5R6BB225; Manuf_Part_2: C0603C225K8PACTU; Manuf_2: KEMET
C79 C88 C93 C104 C105 = Cap_4.7uF_X5R_10%_0603: Capacitor,4.7uF,16V, X5R,10%,0603,YAGEO; Manuf_Part_1: CC0603KRX5R7BB475; Order: CC0603KRX5R7BB105
CN1 = RCA_SMD: RCA Phono Jack, Right Angle, SMD, Yellow; Manuf_Part_1: JBB0819100002; Manuf_1: Jiubaba
CN10 = PJ3028B-3_GR: Connector Jack Stereo 3.5mm, female SMT, Green (Line output); Manuf_1: qiaod; Manuf_Part_2: PJ30280-3_GR
CN11 = PJ3028B-3_BE: Connector Jack Stereo 3.5mm, female SMT, Blue (Line input); Manuf_1: qiaod; Manuf_Part_2: PJ30280-3_BE
JP3 JP4 = Jumper2: Fitted: NO
R6 = Res_75_1%_0402: Resistor,75,0402,1%,YAGEO; Manuf_Part_1: RC0402FR-0775RL; Order: 311-75.0LRTR-ND
R7 R10 = Res_100_1%_0402: Resistor,100,0402,1%,YAGEO; Manuf_Part_1: RC0402FR-07100RL; Order: 9239111
R8 R80 = Res_NA_0402: Resistor,[NA],0402; Fitted: NO
R9 R22 = Res_1M_1%_0402: Resistor,1M,0402,1%,YAGEO; Manuf_Part_1: RC0402FR-071ML
R47 R87 = Res_10K_1%_0402: as R60 on sheet ST_LINK_V2-1
R76 R83 = Res_0_5%_0402: Resistor,0,0402,5%,YAGEO; Manuf_Part_1: RC0402JR-070RL; Order: 2363467
R102 R121 = Res_20_1%_0402: Resistor,20,0402,1%,YAGEO; Manuf_Part_1: RC0402FR-0720RL
TP3 = TP1: Test Point; Fitted: NO
U1 U2 = 74LVC1G04SE: Single inverter gate with a standard push-pull output. (1.65V to 5.5V); Manuf_Part_1: 74LVC1G04SE-7; Manuf_1: DIODES; Order: 1845218; ECCN_US/EU: EAR99/NEC
U11 = WM8994ECS/R: Multi-Channel Audio Hub CODEC for Smartphones; Manuf_1: Cirrus Logic; ECCN_US/EU: EAR99/NEC
U20 U21 = IMP34DT05TR: MEMS audio sensor omnidirectional digital microphone for industrial applications; Manuf_1: STMICROELECTRONICS; ECCN_US/EU: EAR99/NEC; provided: SUBCO with ST control

## Sheet USB_OTG_FS.SchDoc: USB OTG FS with Micro A-B connector
size A4; Date: 25-FEB-2015; Author: A.B; CompanyName: STMicroelectronics; Address1: 12, Rue Jules HOROWITZ; Address2: 38019 Grenoble; Address3: FRANCE; DocumentNumber: MB1191; Revision: B-02; SheetNumber: 9; SheetTotal: 14; Project: STM32F746G-DISCO
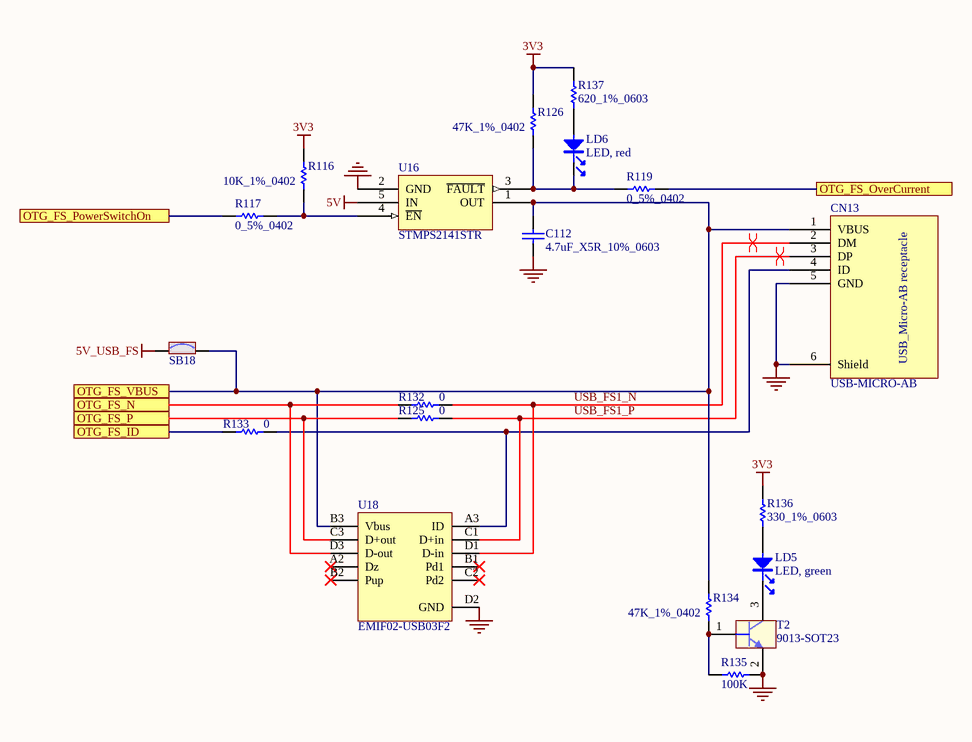
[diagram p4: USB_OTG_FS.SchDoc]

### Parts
C112  4.7uF_X5R_10%_0603  [0603C]
CN13  USB-MICRO-AB  [USB-MICRO-AB]
LD5  LED, green  [0603D]
LD6  LED, red  [0603D]
R116  10K_1%_0402  [0402R]
R117  0_5%_0402  [0402R]
R119  0_5%_0402  [0402R]
R125  0  [0402R]
R126  47K_1%_0402  [0402R]
R132  0  [0402R]
R133  0  [0402R]
R134  47K_1%_0402  [0402R]
R135  100K  [0402R]
R136  330_1%_0603  [0603R]
R137  620_1%_0603  [0603R]
SB18  Solder Bridge ON  [JP2_SMD]  (value not drawn)
T2  9013-SOT23  [SOT23]
U16  STMPS2141STR  [SOT23-5L]
U18  EMIF02-USB03F2  [Flip Chip]

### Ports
OTG_FS_ID, OTG_FS_N, OTG_FS_OverCurrent, OTG_FS_P, OTG_FS_PowerSwitchOn, OTG_FS_VBUS

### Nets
3V3: R116.2 R126.2 R136.2 R137.2
5V: U16.5(IN)
5V_USB_FS: SB18.1
GND: C112.1 CN13.5(GND) CN13.6(Shield) R135.2 T2.2(E) U16.2(GND) U18.D2(GND)
OTG_FS_ID: R133.1 ; port OTG_FS_ID
OTG_FS_N: R132.1 U18.D3(D-out) ; port OTG_FS_N
OTG_FS_OverCurrent: R119.2 ; port OTG_FS_OverCurrent
OTG_FS_P: R125.1 U18.C3(D+out) ; port OTG_FS_P
OTG_FS_PowerSwitchOn: R117.1 ; port OTG_FS_PowerSwitchOn
OTG_FS_VBUS: C112.2 CN13.1(VBUS) R134.2 SB18.2 U16.1(OUT) U18.B3(Vbus) ; port OTG_FS_VBUS
USB_FS1_N: CN13.2(DM) R132.2 U18.D1(D-in)
USB_FS1_P: CN13.3(DP) R125.2 U18.C1(D+in)
NetCN13_4: CN13.4(ID) R133.2 U18.A3(ID)
NetLD5_1: LD5.1 R136.1
NetLD5_2: LD5.2 T2.3(C)
NetLD6_1: LD6.1 R137.1
NetLD6_2: LD6.2 R119.1 R126.1 U16.3(~{FAULT})
NetR116_1: R116.1 R117.2 U16.4(~{EN})
NetR134_1: R134.1 R135.1 T2.1(B)

Not connected (* = marked no-connect by the designer): U18 A2(Dz)* B1(Pd1)* B2(Pup)* C2(Pd2)*

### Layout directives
differential pair: USB_FS1_N, USB_FS1_P

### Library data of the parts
C112 = Cap_4.7uF_X5R_10%_0603: as C79 on sheet AUDIO
CN13 = USB-MICRO-AB: USB-MICRO-AB, 47590-0001, SMT, MOLEX; Ref St: xxxxxxx
LD5 = LED_green: LED, green, 0603; Manuf_1: everlight; Manuf_Part_1: 19-213SYGC/S530-E2/TR8; ECCN_US/EU: EAR99/NEC
LD6 = LED_red: as LD2 on sheet ST_LINK_V2-1
R116 = Res_10K_1%_0402: as R60 on sheet ST_LINK_V2-1
R117 R119 = Res_0_5%_0402: Resistor,0,0402,5%,YAGEO; Manuf_Part_1: RC0402JR-070RL; Value: 0; Order: 2363467
R125 R132 R133 = Res_0_5%_0402: as R76 on sheet AUDIO
R126 R134 = Res_47K_1%_0402: Resistor,47K,0402,1%,YAGEO; Manuf_Part_1: RC0402FR-0747KL; Order: 9239430
R135 = Res_100K_1%_0402: as R72 on sheet ST_LINK_V2-1
R136 = Res_330_1%_0603: Resistor,330,0603,1%,YAGEO; Manuf_Part_1: RT0603FRE07330RL; Value: 330; Order: 1500622RL
R137 = Res_620_1%_0603: Resistor,620,0603,1%,VISHAY; Manuf_Part_1: CRCW0603620RFKEA; Manuf_1: VISHAY DRALORIC; Value: 620; Order: 2122341
SB18 = SB_ON: Solder: YES
T2 = 9013-SOT23: as T3 on sheet ST_LINK_V2-1
U16 = STMPS2141STR: Enhanced single channel power switches; Manuf_1: STM; Provided: ST; ECCN_US/EU: EAR99/NEC; Ref St: 9159003
U18 = EMIF02-USB03F2: 2-line IPAD, EMI filter including ESD protection; Manuf_1: STM; Provided: ST; ECCN_US/EU: EAR99/NEC; Ref St: 9179037

## Sheet Peripherals.SchDoc: Joystick, ACP, LEDs and Push Button
size A4; Date: 25-FEB-2015; Author: A.B; CompanyName: STMicroelectronics; Address1: 12, Rue Jules HOROWITZ; Address2: 38019 Grenoble; Address3: FRANCE; DocumentNumber: MB1191; Revision: B-02; SheetNumber: 5; SheetTotal: 14; Project: STM32F746G-DISCO
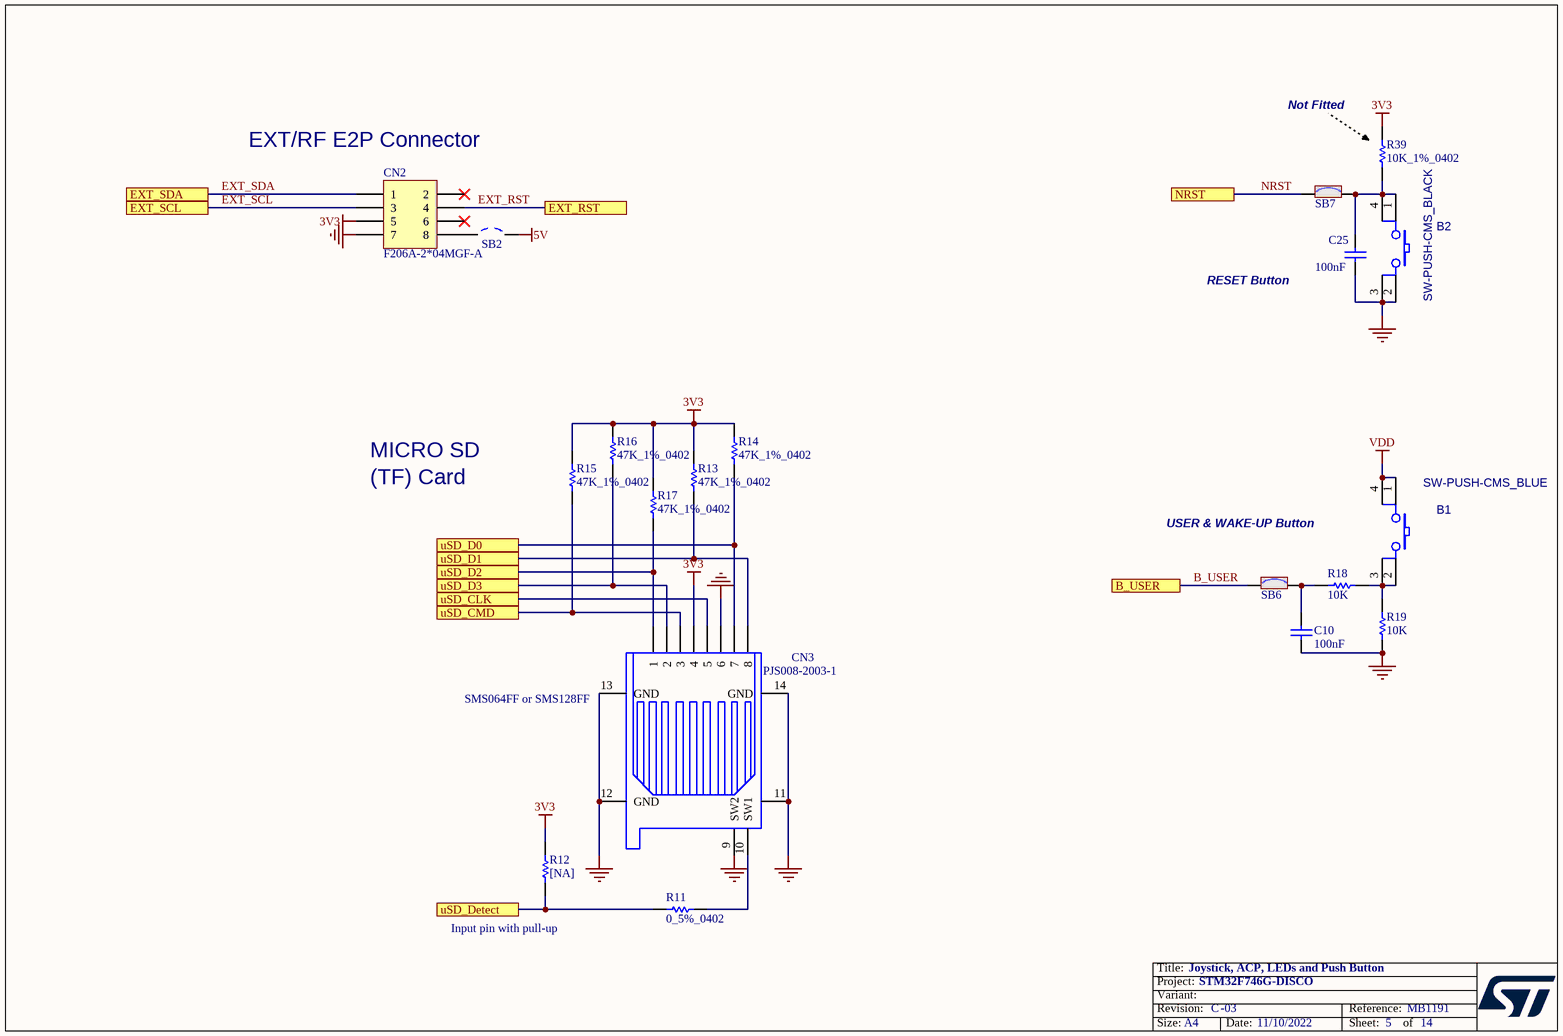
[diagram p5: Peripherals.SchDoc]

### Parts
B1  SW-PUSH-CMS_BLUE  [BP1CMS]
B2  SW-PUSH-CMS_BLACK  [BP1CMS]
C10  100nF  [0402C]
C25  100nF  [0402C]
CN2  F206A-2*04MGF-A  [SSM-104-L-DH]
CN3  PJS008-2003-1  [PJS008-2003-1]
R11  0_5%_0402  [0402R]
R12  [NA]  [0402R]
R13  47K_1%_0402  [0402R]
R14  47K_1%_0402  [0402R]
R15  47K_1%_0402  [0402R]
R16  47K_1%_0402  [0402R]
R17  47K_1%_0402  [0402R]
R18  10K  [0402R]
R19  10K  [0402R]
R39  10K_1%_0402  [0402R]
SB2  Solder Bridge OFF  [JP2_SMD]  (value not drawn)
SB6  Solder Bridge ON  [JP2_SMD]  (value not drawn)
SB7  Solder Bridge ON  [JP2_SMD]  (value not drawn)

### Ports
B_USER, EXT_RST, EXT_SCL, EXT_SDA, NRST, uSD_CLK, uSD_CMD, uSD_D0, uSD_D1, uSD_D2, uSD_D3, uSD_Detect

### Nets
3V3: CN2.5 CN3.4 R12.2 R13.2 R14.2 R15.2 R16.2 R17.2 R39.2
5V: SB2.2
GND: B2.2 B2.3 C10.1 C25.1 CN2.7 CN3.6 CN3.9(SW2) CN3.11(GND) CN3.12(GND) CN3.13(GND) CN3.14(GND) R19.1
VDD: B1.1 B1.4
B_USER: SB6.1 ; port B_USER
EXT_RST: CN2.4 ; port EXT_RST
EXT_SCL: CN2.3 ; port EXT_SCL  [project net ARD_D15]
EXT_SDA: CN2.1 ; port EXT_SDA  [project net ARD_D14]
NRST: SB7.1 ; port NRST  [project net DCMI_NRST]
PC8: CN3.7 R14.1 ; port uSD_D0
PC9: CN3.8 R13.1 ; port uSD_D1
PC10: CN3.1 R17.1 ; port uSD_D2
PC11: CN3.2 R16.1 ; port uSD_D3
PC12: CN3.5 ; port uSD_CLK
PC13: R11.1 R12.1 ; port uSD_Detect
PD2: CN3.3 R15.1 ; port uSD_CMD
NetB1_2: B1.2 B1.3 R18.2 R19.2
NetB2_1: B2.1 B2.4 C25.2 R39.1 SB7.2
NetC10_2: C10.2 R18.1 SB6.2
NetCN2_8: CN2.8 SB2.1
NetCN3_10: CN3.10(SW1) R11.2

Not connected (* = marked no-connect by the designer): CN2 2* 6*

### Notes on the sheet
- (near R39) Not Fitted
- (near CN2) EXT/RF E2P Connector
- RESET Button
- MICRO SD
- (TF) Card
- USER & WAKE-UP Button
- (near CN3) SMS064FF or SMS128FF
- (near R12) Input pin with pull-up

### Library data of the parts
B1 = SW-PUSH-CMS_BLUE: Non-Open Push-Button 0.1A 24V; Manuf_2: FARNELL; Manuf_Part_2: 535-930; Manuf_1: wealthmetal; Manuf_Part_1: TD0341X-G01-BLU; Ref St: 9180120
B2 = SW-PUSH-CMS_BLACK: Non-Open Push-Button 0.1A 24V; Manuf_2: FARNELL; Manuf_Part_2: 535-930; Manuf_1: wealthmetal; Manuf_Part_1: TD0341X-G01-BLA; Ref St: 9180120
C10 C25 = Cap_100nF_X7R_10%_0402: as C61 on sheet ST_LINK_V2-1
CN2 = F206A-2*04MGF-A: Header, 5-Pins, Horizontal Dual row, female SMD; Manuf_2: SAMTEC; Manuf_1: TOWNES
CN3 = microSD-PJS008-2003: Memory Card Connectors MicroSD Card Conn Revrs Mnt Push-Push; Manuf_1: YAMAICHI
R11 = Res_0_5%_0402: as R117 on sheet USB_OTG_FS
R12 = Res_NA_0402: Resistor,[NA],0402; Fitted: NO
R13-R17 = Res_47K_1%_0402: as R126 on sheet USB_OTG_FS
R18 R19 = Res_10K_1%_0402: as R60 on sheet ST_LINK_V2-1
R39 = Res_10K_1%_0402: Resistor,10K,0402,1%,YAGEO; Manuf_Part_1: RC0402FR-0710KL; Fitted: NO
SB2 = SB_OFF: Solder: NO
SB6 SB7 = SB_ON: Solder: YES

## Sheet QSPI.SchDoc: Quad SPI Flash Memory (MICRON)
size A4; Date: 25-FEB-2015; Author: A.B; CompanyName: STMicroelectronics; Address1: 12, Rue Jules HOROWITZ; Address2: 38019 Grenoble; Address3: FRANCE; DocumentNumber: MB1191; Revision: B-02; SheetNumber: 7; SheetTotal: 14; Project: STM32F746G-DISCO
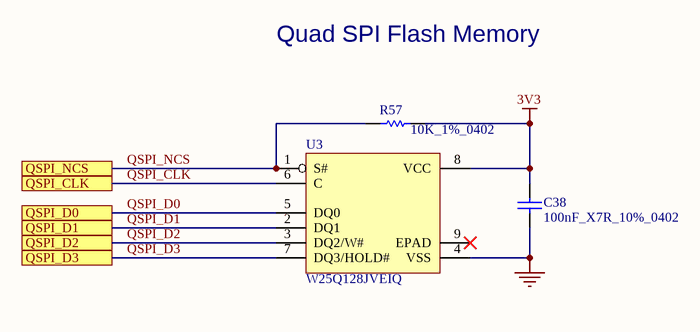
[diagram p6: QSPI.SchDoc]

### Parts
C38  100nF_X7R_10%_0402  [0402C]
R57  10K_1%_0402  [0402R]
U3  W25Q128JVEIQ  [W-PDFN-8_8X6_P127]

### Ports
QSPI_CLK, QSPI_D0, QSPI_D1, QSPI_D2, QSPI_D3, QSPI_NCS

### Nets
3V3: C38.2 R57.2 U3.8(VCC)
GND: C38.1 U3.4(VSS)
QSPI_CLK: U3.6(C) ; port QSPI_CLK  [project net PB2]
QSPI_D0: U3.5(DQ0) ; port QSPI_D0  [project net PD11]
QSPI_D1: U3.2(DQ1) ; port QSPI_D1  [project net PD12]
QSPI_D2: U3.3(DQ2/W#) ; port QSPI_D2  [project net PE2]
QSPI_D3: U3.7(DQ3/HOLD#) ; port QSPI_D3  [project net PD13]
QSPI_NCS: R57.1 U3.1(S#) ; port QSPI_NCS  [project net PB6]

Not connected (* = marked no-connect by the designer): U3 9(EPAD)*

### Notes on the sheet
- Quad SPI Flash Memory

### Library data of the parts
C38 = Cap_100nF_X7R_10%_0402: as C61 on sheet ST_LINK_V2-1
R57 = Res_10K_1%_0402: as R60 on sheet ST_LINK_V2-1
U3 = MT25QL128ABA1EW9-0SIT: 128Mb, 3V, Multiple I/O Serial Flash Memory, Quad/Dual; Manuf_1: Winbond; ECCN_US/EU: 3A991/NEC; Provided: ST

## Sheet LCD-43.SchDoc: LCD 4.3" with Capacitive Touch
size A4; Date: 25-FEB-2015; Author: A.B; CompanyName: STMicroelectronics; Address1: 12, Rue Jules HOROWITZ; Address2: 38019 Grenoble; Address3: FRANCE; DocumentNumber: MB1191; Revision: B-02; SheetNumber: 14; SheetTotal: 14; Project: STM32F746G-DISCO
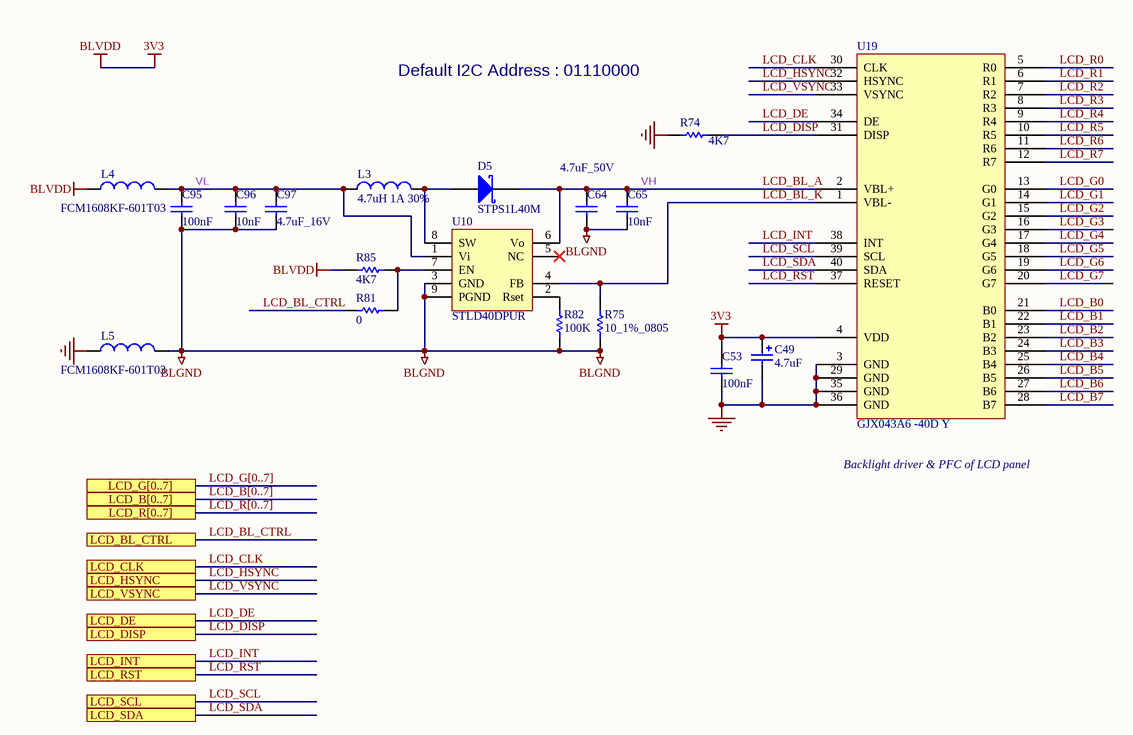
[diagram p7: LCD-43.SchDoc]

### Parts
C49  4.7uF  [TAN-A]
C53  100nF  [0402C]
C64  4.7uF_50V  [1206C]
C65  10nF  [0603C]
C95  100nF  [0603C]
C96  10nF  [0603C]
C97  4.7uF_16V  [1206C]
D5  STPS1L40M  [DO216-AA]
L3  4.7uH 1A 30%  [1210L]
L4  FCM1608KF-601T03  [0603L]
L5  FCM1608KF-601T03  [0603L]
R74  4K7  [0402R]
R75  10_1%_0805  [0805R]
R81  0  [0402R]
R82  100K  [0402R]
R85  4K7  [0402R]
U10  STLD40DPUR  [QFN8_0R65_3X3_ST]
U19  GJX043A6 -40D Y  [LCD_Kunjian_ HT043C_40P_P080_FLEX_FOLDED]

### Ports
LCD_B[0..7], LCD_BL_CTRL, LCD_CLK, LCD_DE, LCD_DISP, LCD_G[0..7], LCD_HSYNC, LCD_INT, LCD_R[0..7], LCD_RST, LCD_SCL, LCD_SDA, LCD_VSYNC

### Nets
3V3: C49.1 C53.2 L4.1 R85.2 U19.4(VDD)  [also labelled BLVDD]
BLGND: C64.2 C65.1 C95.1 C96.1 C97.2 L5.2 R75.1 R82.2 U10.3(GND) U10.9(PGND)
GND: C49.2 C53.1 L5.1 R74.2 U19.3(GND) U19.29(GND) U19.35(GND) U19.36(GND)
LCD_B0: U19.21(B0)
LCD_B1: U19.22(B1)
LCD_B2: U19.23(B2)
LCD_B3: U19.24(B3)
LCD_B4: U19.25(B4)
LCD_B5: U19.26(B5)
LCD_B6: U19.27(B6)
LCD_B7: U19.28(B7)
LCD_BL_A: C64.1 C65.2 D5.2(K) U10.6(Vo) U19.2(VBL+)  [also labelled VH]
LCD_BL_CTRL: R81.2 ; port LCD_BL_CTRL
LCD_BL_K: R75.2 U10.4(FB) U19.1(VBL-)
LCD_CLK: U19.30(CLK) ; port LCD_CLK
LCD_DE: U19.34(DE) ; port LCD_DE
LCD_DISP: R74.1 U19.31(DISP) ; port LCD_DISP
LCD_G0: U19.13(G0)
LCD_G1: U19.14(G1)
LCD_G2: U19.15(G2)
LCD_G3: U19.16(G3)
LCD_G4: U19.17(G4)
LCD_G5: U19.18(G5)
LCD_G6: U19.19(G6)
LCD_G7: U19.20(G7)
LCD_HSYNC: U19.32(HSYNC) ; port LCD_HSYNC
LCD_INT: U19.38(INT) ; port LCD_INT
LCD_R0: U19.5(R0)
LCD_R1: U19.6(R1)
LCD_R2: U19.7(R2)
LCD_R3: U19.8(R3)
LCD_R4: U19.9(R4)
LCD_R5: U19.10(R5)
LCD_R6: U19.11(R6)
LCD_R7: U19.12(R7)
LCD_RST: U19.37(RESET) ; port LCD_RST  [project net DCMI_NRST]
LCD_SCL: U19.39(SCL) ; port LCD_SCL  [project net AUDIO_SCL]
LCD_SDA: U19.40(SDA) ; port LCD_SDA  [project net AUDIO_SDA]
LCD_VSYNC: U19.33(VSYNC) ; port LCD_VSYNC
VL: C95.2 C96.2 C97.1 L3.1 L4.2 U10.1(Vi)
NetD5_1: D5.1(A) L3.2 U10.8(SW)
NetR81_1: R81.1 R85.1 U10.7(EN)
NetR82_1: R82.1 U10.2(Rset)

Not connected (* = marked no-connect by the designer): U10 5(NC)*

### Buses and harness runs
bus LCD_B[0..7] = port LCD_B[0..7]
bus LCD_G[0..7] = port LCD_G[0..7]
bus LCD_R[0..7] = port LCD_R[0..7]

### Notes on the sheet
- Default I2C Address : 01110000
- Backlight driver & PFC of LCD panel

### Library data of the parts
C49 = Cap_4.7uF_POL_10%_TANA: Polarized Capacitor,4.7uF,16V,10%,typeA,AVX; Manuf_Part_1: TAJA475K016R
C53 = Cap_100nF_X7R_10%_0402: as C61 on sheet ST_LINK_V2-1
C64 = Cap_4.7uF_X7R_10%_1206: Capacitor,4.7uF,50V, X7R,10%,1206,AVX; Manuf_Part_1: 12065C475KAT2A
C65 C96 = Cap_10nF_X7R_10%_0603: as C94 on sheet ST_LINK_V2-1
C95 = Cap_100nF_X7R_10%_0603: Capacitor,100nF,16V,X7R,10%,0603,YAGEO; Manuf_Part_1: CC0603KRX7R9BB104
C97 = Cap_4.7uF_X5R_10%_1206: Capacitor,4.7uF,16V, X5R,10%,1206,AVX; Manuf_Part_1: 1206YD475KAT2A
D5 = STPS1L40M: Low Drop power Schottky rectifier(1A, 40V, 0.4V); Manuf_1: STM; Provided: ST; Ref St: 9151085; ECCN_US/EU: EAR99/NEC
L3 = Ind_4.7uH_1A_30%: FIXED IND 4.7UH 1A 180 MOHM 30% SMD; Manuf_Part_1: LQH32PN4R7NN0L; Manuf_1: MURATA; Order: 490-5338-1-ND
L4 L5 = BEAD_600R_350MA_0603: Bead,600R,350mA,0603,FCM1608KF-601T03,Tai-tech; Manuf_2: TDK; Manuf_Part_2: MPZ1608S300A; Manuf_Part_3: BLM18PG121SN1D; Manuf_3: MURATA; Value: 100uH; Description_2: Bead,30R,5A,0603,MPZ1608S300A,TDK; Description_3: Bead,120R,2A,0603,BLM18PG121SN1D,MURATA
R74 R85 = Res_4K7_1%_0402: as R97 on sheet ST_LINK_V2-1
R75 = Res_10_1%_0805: Resistor,10,0805,1%,Stackpole,1/4W; Manuf_Part_1: RNCP0805FTD10R0; Manuf_1: Stackpole Electronics Inc; Value: 10
R81 = Res_0_5%_0402: as R76 on sheet AUDIO
R82 = Res_100K_1%_0402: as R72 on sheet ST_LINK_V2-1
U10 = STLD40DPUR: White LED power supply for large display backlight, QFN8; Manuf_1: STM; ECCN_US/EU: EAR99/NEC; Ref St: xxxxxxxxx; Provided: ST
U19 = HT043C: 4.3 inch TFT 480*272 pixels with LED Backlight and Capacitive touch panel, high luminance; Manuf_1: Shenzhen GJX Electronics Technology Co.,Ltd; ECCN_US/EU: EAR99/NEC

## Sheet Arduino_ Connectors.SchDoc: Arduino UNO connectors
size A4; Date: 25-FEB-2015; Author: A.B; CompanyName: STMicroelectronics; Address1: 12, Rue Jules HOROWITZ; Address2: 38019 Grenoble; Address3: FRANCE; DocumentNumber: MB1191; Revision: B-02; SheetNumber: 8; SheetTotal: 14; Project: STM32F746G-DISCO
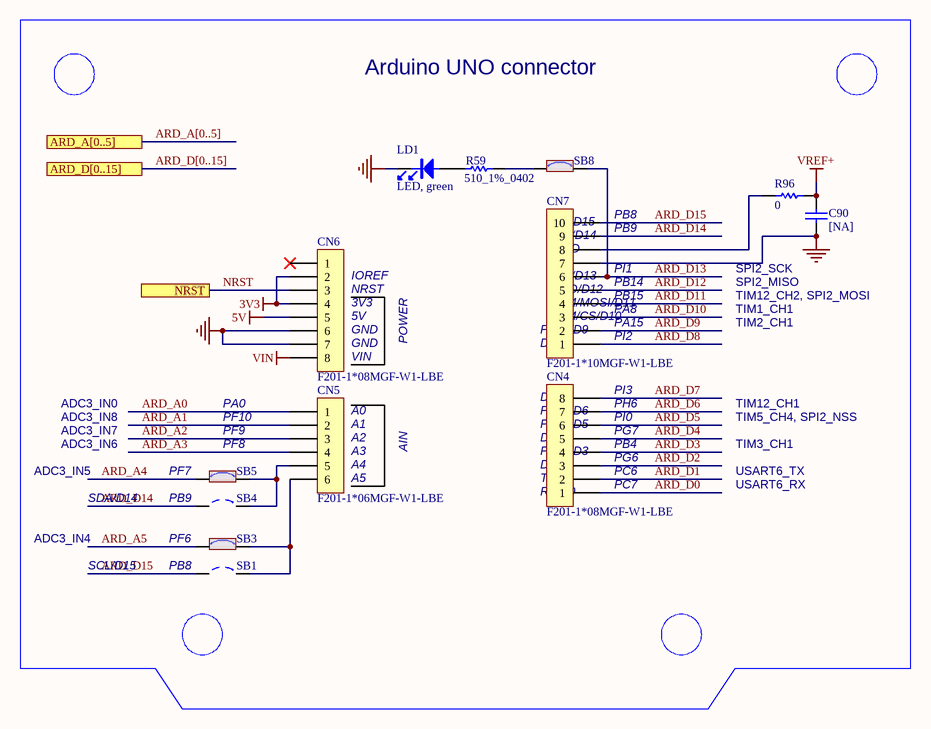
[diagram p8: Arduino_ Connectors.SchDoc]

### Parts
C90  [NA]  [0402C]
CN4  F201-1*08MGF-W1-LBE  [F201-1*08MGF-W1-BA]
CN5  F201-1*06MGF-W1-LBE  [F201-1*06MGF-W1-BA]
CN6  F201-1*08MGF-W1-LBE  [F201-1*08MGF-W1-BA]
CN7  F201-1*10MGF-W1-LBE  [F201-1*10MGF-W1-BA]
LD1  LED, green  [0603D]
R59  510_1%_0402  [0402R]
R96  0  [0402R]
SB1  Solder Bridge OFF  [JP2_SMD]  (value not drawn)
SB3  Solder Bridge ON  [JP2_SMD]  (value not drawn)
SB4  Solder Bridge OFF  [JP2_SMD]  (value not drawn)
SB5  Solder Bridge ON  [JP2_SMD]  (value not drawn)
SB8  Solder Bridge ON  [JP2_SMD]  (value not drawn)

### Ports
ARD_A[0..5], ARD_D[0..15], NRST

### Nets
3V3: CN6.2 CN6.4
5V: CN6.5
GND: C90.1 CN6.6 CN6.7 CN7.7 LD1.2
VIN: CN6.8
VREF+: C90.2 R96.2
ARD_A0: CN5.1
ARD_A1: CN5.2
ARD_A2: CN5.3
ARD_A3: CN5.4
ARD_A4: SB5.1
ARD_A5: SB3.1
ARD_D0: CN4.1
ARD_D1: CN4.2
ARD_D2: CN4.3
ARD_D3: CN4.4
ARD_D4: CN4.5
ARD_D5: CN4.6
ARD_D6: CN4.7
ARD_D7: CN4.8
ARD_D8: CN7.1
ARD_D9: CN7.2
ARD_D10: CN7.3
ARD_D11: CN7.4
ARD_D12: CN7.5
ARD_D13: CN7.6 SB8.2
ARD_D14: CN7.9 SB4.1
ARD_D15: CN7.10 SB1.1
NRST: CN6.3 ; port NRST  [project net DCMI_NRST]
NetCN5_5: CN5.5 SB4.2 SB5.2
NetCN5_6: CN5.6 SB1.2 SB3.2
NetCN7_8: CN7.8 R96.1
NetLD1_1: LD1.1 R59.1
NetR59_2: R59.2 SB8.1

Not connected (* = marked no-connect by the designer): CN6 1*

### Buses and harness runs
bus ARD_A[0..5] = port ARD_A[0..5]
bus ARD_D[0..15] = port ARD_D[0..15]

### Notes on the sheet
- Arduino UNO connector
- PB8
- (near CN6) IOREF
- (near CN6) NRST
- (near CN7) SDA/D14
- (near CN7) SCL/D15
- (near CN7) SCK/D13
- (near CN7) MISO/D12
- (near CN7) AVDD
- (near CN7) GND
- (near CN7) PB14
- (near CN7) PI1
- (near CN7) PB9
- SPI2_MISO
- SPI2_SCK
- (near CN6) 3V3
- (near CN6) 5V
- (near CN6) GND
- POWER
- (near CN7) D8
- (near CN7) PWM/D9
- (near CN7) PWM/CS/D10
- (near CN7) PWM/MOSI/D11
- (near CN7) PI2
- (near CN7) PA15
- (near CN7) PA8
- (near CN7) PB15
- TIM2_CH1
- TIM1_CH1
- TIM12_CH2, SPI2_MOSI
- ADC3_IN8
- ADC3_IN0
- PA0
- PF10
- (near CN5) A0
- (near CN5) A1
- (near CN6) VIN
- (near CN4) PWM/D5
- (near CN4) PWM/D6
- (near CN4) D7
- (near CN4) PI0
- (near CN4) PH6
- PI3
- TIM5_CH4, SPI2_NSS
- TIM12_CH1
- ADC3_IN5
- ADC3_IN6
- ADC3_IN7
- PF7
- (near SB5) PF9
- (near SB5) PF8
- (near CN5) A2
- (near CN5) A3
- (near CN5) A4
- (near CN5) A5
- AIN
- (near CN4) TX/D1
- (near CN4) D2
- (near CN4) D4
- (near CN4) PWM/D3
- (near CN4) PC6
- (near CN4) PG6
- (near CN4) PB4
- (near CN4) PG7
- (near CN4) PC7
- USART6_RX
- USART6_TX
- TIM3_CH1
- ADC3_IN4
- SDA/D14
- PF6
- PB9
- (near CN4) RX/D0
- SCL/D15

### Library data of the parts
C90 = Cap_NA_0402: Capacitor,NA,0402; Fitted: NO
CN4 CN6 = F201-1*08MGF-W1-BA: Header, 8-Pins, Single row, female SMD; Manuf_1: TOWNES; Manuf_Part_2: SSW-108-22-L-S-VS; Manuf_2: SAMTEC
CN5 = F201-1*06MGF-W1-BA: Header, 6-Pins, Single row, female SMD; Manuf_1: TOWNES; Manuf_Part_2: SSW-106-22-L-S-VS; Manuf_2: SAMTEC
CN7 = F201-1*10MGF-W1-BA: Header, 10-Pins, Single row, female SMD; Manuf_1: TOWNES; Manuf_Part_2: SSW-110-22-L-S-VS; Manuf_2: SAMTEC
LD1 = LED_green: as LD5 on sheet USB_OTG_FS
R59 = Res_510_1%_0402: Resistor,510,0402,1%,YAGEO; Manuf_Part_1: RC0402FR-07510L; Value: 510
R96 = Res_0_5%_0402: as R76 on sheet AUDIO
SB1 SB4 = SB_OFF: Solder: NO
SB3 SB5 SB8 = SB_ON: Solder: YES

## Sheet SDRAM.SchDoc: SDRAM (MICRON)
size A4; Date: 25-FEB-2015; Author: A.B; CompanyName: STMicroelectronics; Address1: 12, Rue Jules HOROWITZ; Address2: 38019 Grenoble; Address3: FRANCE; DocumentNumber: MB1191; Revision: B-02; SheetNumber: 10; SheetTotal: 14; Project: STM32F746G-DISCO
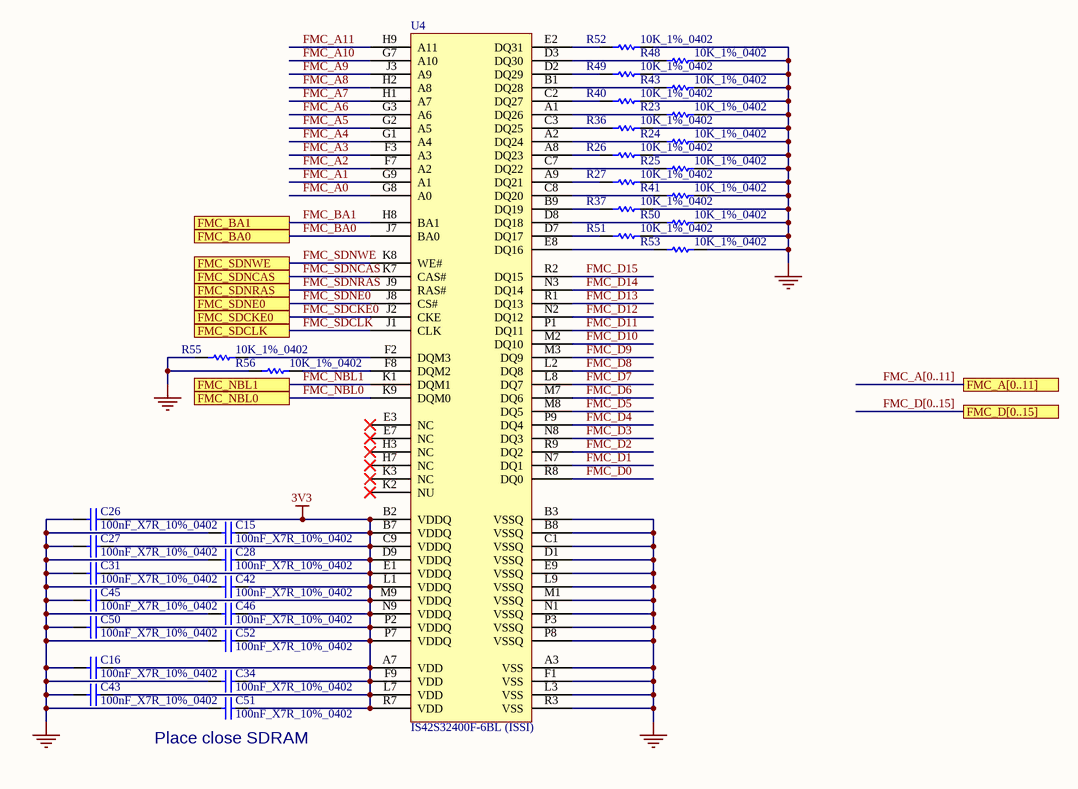
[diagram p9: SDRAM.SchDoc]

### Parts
C15  100nF_X7R_10%_0402  [0402C]
C16  100nF_X7R_10%_0402  [0402C]
C26  100nF_X7R_10%_0402  [0402C]
C27  100nF_X7R_10%_0402  [0402C]
C28  100nF_X7R_10%_0402  [0402C]
C31  100nF_X7R_10%_0402  [0402C]
C34  100nF_X7R_10%_0402  [0402C]
C42  100nF_X7R_10%_0402  [0402C]
C43  100nF_X7R_10%_0402  [0402C]
C45  100nF_X7R_10%_0402  [0402C]
C46  100nF_X7R_10%_0402  [0402C]
C50  100nF_X7R_10%_0402  [0402C]
C51  100nF_X7R_10%_0402  [0402C]
C52  100nF_X7R_10%_0402  [0402C]
R23  10K_1%_0402  [0402R]
R24  10K_1%_0402  [0402R]
R25  10K_1%_0402  [0402R]
R26  10K_1%_0402  [0402R]
R27  10K_1%_0402  [0402R]
R36  10K_1%_0402  [0402R]
R37  10K_1%_0402  [0402R]
R40  10K_1%_0402  [0402R]
R41  10K_1%_0402  [0402R]
R43  10K_1%_0402  [0402R]
R48  10K_1%_0402  [0402R]
R49  10K_1%_0402  [0402R]
R50  10K_1%_0402  [0402R]
R51  10K_1%_0402  [0402R]
R52  10K_1%_0402  [0402R]
R53  10K_1%_0402  [0402R]
R55  10K_1%_0402  [0402R]
R56  10K_1%_0402  [0402R]
U4  IS42S32400F-6BL (ISSI)  [FBGA90_0R8_8X13]

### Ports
FMC_A[0..11], FMC_BA0, FMC_BA1, FMC_D[0..15], FMC_NBL0, FMC_NBL1, FMC_SDCKE0, FMC_SDCLK, FMC_SDNCAS, FMC_SDNE0, FMC_SDNRAS, FMC_SDNWE

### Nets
3V3: C15.2 C16.2 C26.2 C27.2 C28.2 C31.2 C34.2 C42.2 C43.2 C45.2 C46.2 C50.2 C51.2 C52.2 U4.A7(VDD) U4.B2(VDDQ) U4.B7(VDDQ) U4.C9(VDDQ) U4.D9(VDDQ) U4.E1(VDDQ) U4.F9(VDD) U4.L1(VDDQ) U4.L7(VDD) U4.M9(VDDQ) U4.N9(VDDQ) U4.P2(VDDQ) U4.P7(VDDQ) U4.R7(VDD)
GND: C15.1 C16.1 C26.1 C27.1 C28.1 C31.1 C34.1 C42.1 C43.1 C45.1 C46.1 C50.1 C51.1 C52.1 R23.2 R24.2 R25.2 R26.2 R27.2 R36.2 R37.2 R40.2 R41.2 R43.2 R48.2 R49.2 R50.2 R51.2 R52.2 R53.2 R55.1 R56.1 U4.A3(VSS) U4.B3(VSSQ) U4.B8(VSSQ) U4.C1(VSSQ) U4.D1(VSSQ) U4.E9(VSSQ) U4.F1(VSS) U4.L3(VSS) U4.L9(VSSQ) U4.M1(VSSQ) U4.N1(VSSQ) U4.P3(VSSQ) U4.P8(VSSQ) U4.R3(VSS)
FMC_A0: U4.G8(A0)
FMC_A1: U4.G9(A1)
FMC_A2: U4.F7(A2)
FMC_A3: U4.F3(A3)
FMC_A4: U4.G1(A4)
FMC_A5: U4.G2(A5)
FMC_A6: U4.G3(A6)
FMC_A7: U4.H1(A7)
FMC_A8: U4.H2(A8)
FMC_A9: U4.J3(A9)
FMC_A10: U4.G7(A10)
FMC_A11: U4.H9(A11)
FMC_BA0: U4.J7(BA0) ; port FMC_BA0
FMC_BA1: U4.H8(BA1) ; port FMC_BA1
FMC_D0: U4.R8(DQ0)
FMC_D1: U4.N7(DQ1)
FMC_D2: U4.R9(DQ2)
FMC_D3: U4.N8(DQ3)
FMC_D4: U4.P9(DQ4)
FMC_D5: U4.M8(DQ5)
FMC_D6: U4.M7(DQ6)
FMC_D7: U4.L8(DQ7)
FMC_D8: U4.L2(DQ8)
FMC_D9: U4.M3(DQ9)
FMC_D10: U4.M2(DQ10)
FMC_D11: U4.P1(DQ11)
FMC_D12: U4.N2(DQ12)
FMC_D13: U4.R1(DQ13)
FMC_D14: U4.N3(DQ14)
FMC_D15: U4.R2(DQ15)
FMC_NBL0: U4.K9(DQM0) ; port FMC_NBL0
FMC_NBL1: U4.K1(DQM1) ; port FMC_NBL1
FMC_SDCKE0: U4.J2(CKE) ; port FMC_SDCKE0
FMC_SDCLK: U4.J1(CLK) ; port FMC_SDCLK
FMC_SDNCAS: U4.K7(CAS#) ; port FMC_SDNCAS
FMC_SDNE0: U4.J8(CS#) ; port FMC_SDNE0
FMC_SDNRAS: U4.J9(RAS#) ; port FMC_SDNRAS
FMC_SDNWE: U4.K8(WE#) ; port FMC_SDNWE
NetR23_1: R23.1 U4.A1(DQ26)
NetR24_1: R24.1 U4.A2(DQ24)
NetR25_1: R25.1 U4.C7(DQ22)
NetR26_1: R26.1 U4.A8(DQ23)
NetR27_1: R27.1 U4.A9(DQ21)
NetR36_1: R36.1 U4.C3(DQ25)
NetR37_1: R37.1 U4.B9(DQ19)
NetR40_1: R40.1 U4.C2(DQ27)
NetR41_1: R41.1 U4.C8(DQ20)
NetR43_1: R43.1 U4.B1(DQ28)
NetR48_1: R48.1 U4.D3(DQ30)
NetR49_1: R49.1 U4.D2(DQ29)
NetR50_1: R50.1 U4.D8(DQ18)
NetR51_1: R51.1 U4.D7(DQ17)
NetR52_1: R52.1 U4.E2(DQ31)
NetR53_1: R53.1 U4.E8(DQ16)
NetR55_2: R55.2 U4.F2(DQM3)
NetR56_2: R56.2 U4.F8(DQM2)

Not connected (* = marked no-connect by the designer): U4 E3(NC)* E7(NC)* H3(NC)* H7(NC)* K2(NU)* K3(NC)*

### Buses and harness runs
bus FMC_A[0..11] = port FMC_A[0..11]
bus FMC_D[0..15] = port FMC_D[0..15]

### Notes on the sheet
- (near C51) Place close SDRAM

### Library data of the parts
C15 C16 C26-C28 C31 C34 C42 C43 C45 C46 C50-C52 = Cap_100nF_X7R_10%_0402: as C61 on sheet ST_LINK_V2-1
R23-R27 R36 R37 R40 R41 R43 R48-R53 R55 R56 = Res_10K_1%_0402: as R60 on sheet ST_LINK_V2-1
U4 = MT48LC4M32B2B5-6A: SDRAM 128MBIT (4M x 32) 166MHZ 90-VFBGA (8x13); Order: IS42S32400F-6BL-ND; ECCN_US/EU: EAR99/NEC; Provided: SUBCO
